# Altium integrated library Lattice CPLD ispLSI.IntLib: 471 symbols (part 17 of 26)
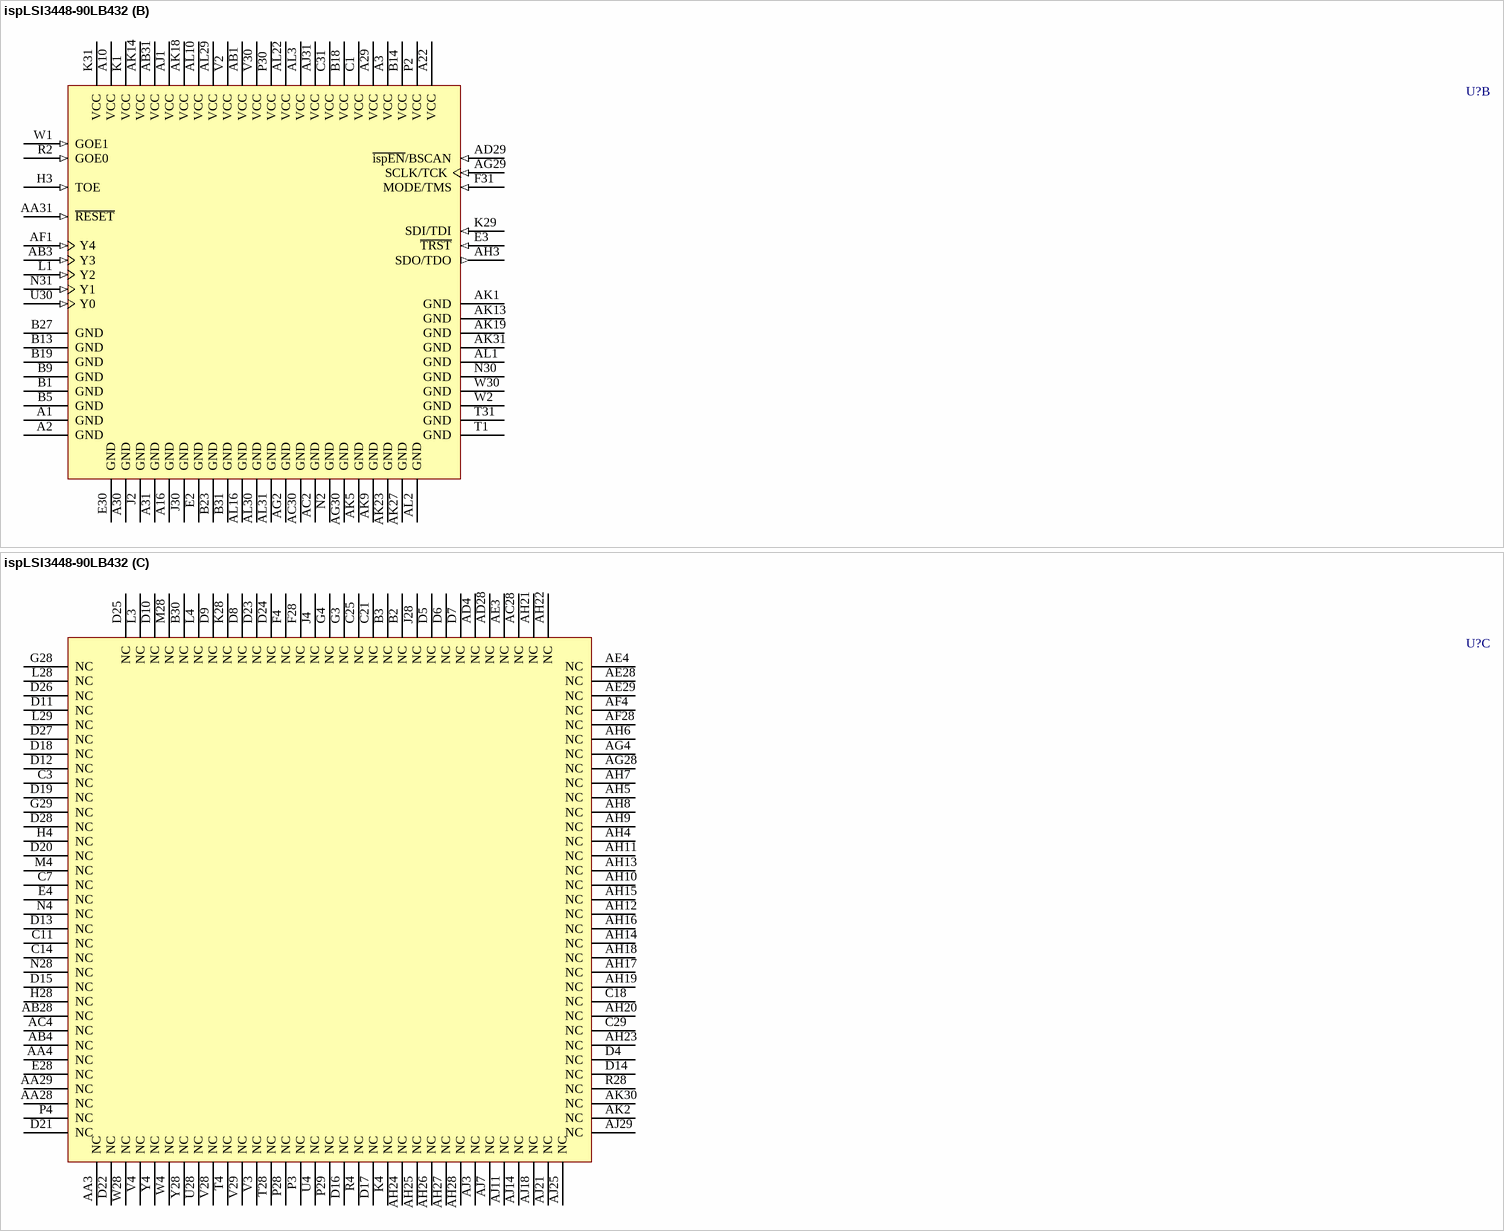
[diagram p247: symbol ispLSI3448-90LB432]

## ispLSI3448-90LB432
designator U?
In-System Programmable High-Density PLD
footprint SBGA432 (BGA, 432-Leads, Body 40x40mm, Pitch 1.27mm)
3D model 3448-SBGA432 (432-Ball Super Ball Grid Array (SBGA432))
part A pins: A4 I/O141 (io), A5 I/O142 (io), A6 I/O145 (io), A7 I/O147 (io), A8 I/O150 (io), A9 I/O152 (io), A11 I/O156 (io), A12 I/O159 (io), A13 I/O161 (io), A14 I/O162 (io), A15 I/O165 (io), A17 I/O170 (io), A18 I/O171 (io), A19 I/O172 (io), A20 I/O174 (io), A21 I/O177 (io), A23 I/O181 (io), A24 I/O183 (io), A25 I/O186 (io), A26 I/O188 (io), A27 I/O191 (io), A28 I/O192 (io), AA1 I/O102 (io), AA2 I/O101 (io), AA30 I/O9 (io), AB2 I/O100 (io), AB29 I/O11 (io), AB30 I/O10 (io), AC1 I/O99 (io), AC3 I/O98 (io), AC29 I/O13 (io), AC31 I/O12 (io), AD1 I/O97 (io), AD2 I/O96 (io), AD3 I/O95 (io), AD30 I/O15 (io), AD31 I/O14 (io), AE1 I/O94 (io), AE2 I/O93 (io), AE30 I/O17 (io), AE31 I/O16 (io), AF2 I/O92 (io), AF3 I/O91 (io), AF29 I/O20 (io), AF30 I/O19 (io), AF31 I/O18 (io), AG1 I/O90 (io), AG3 I/O88 (io), AG31 I/O21 (io), AH1 I/O89 (io), AH2 I/O87 (io), AH29 I/O25 (io), AH30 I/O23 (io), AH31 I/O22 (io), AJ2 I/O86 (io), AJ4 I/O85 (io), AJ5 I/O82 (io), AJ6 I/O79 (io), AJ8 I/O74 (io), AJ9 I/O71 (io), AJ10 I/O69 (io), AJ12 I/O65 (io), AJ13 I/O62 (io), AJ15 I/O57 (io), AJ16 I/O55 (io), AJ17 I/O52 (io), AJ19 I/O49 (io), AJ20 I/O46 (io), AJ22 I/O42 (io), AJ23 I/O40 (io), AJ24 I/O37 (io), AJ26 I/O32 (io), AJ27 I/O29 (io), AJ28 I/O26 (io), AJ30 I/O24 (io), AK3 I/O84 (io), AK4 I/O83 (io), AK6 I/O78 (io), AK7 I/O76 (io), AK8 I/O73 (io), AK10 I/O68 (io), AK11 I/O67 (io), AK12 I/O64 (io), AK15 I/O58 (io), AK16 I/O56 (io), AK17 I/O53 (io), AK20 I/O47 (io), AK21 I/O44 (io), AK22 I/O43 (io), AK24 I/O38 (io), AK25 I/O35 (io), AK26 I/O33 (io), AK28 I/O28 (io), AK29 I/O27 (io), AL4 I/O81 (io), AL5 I/O80 (io), AL6 I/O77 (io), AL7 I/O75 (io), AL8 I/O72 (io), AL9 I/O70 (io), AL11 I/O66 (io), AL12 I/O63 (io), AL13 I/O61 (io), AL14 I/O60 (io), AL15 I/O59 (io), AL17 I/O54 (io), AL18 I/O51 (io), AL19 I/O50 (io), AL20 I/O48 (io), AL21 I/O45 (io), AL23 I/O41 (io), AL24 I/O39 (io), AL25 I/O36 (io), AL26 I/O34 (io), AL27 I/O31 (io), AL28 I/O30 (io), B4 I/O139 (io), B6 I/O144 (io), B7 I/O146 (io), B8 I/O149 (io), B10 I/O154 (io), B11 I/O155 (io), B12 I/O158 (io), B15 I/O164 (io), B16 I/O167 (io), B17 I/O169 (io), B20 I/O175 (io), B21 I/O178 (io), B22 I/O179 (io), B24 I/O184 (io), B25 I/O187 (io), B26 I/O189 (io), B28 I/O194 (io), B29 I/O195 (io), C2 I/O136 (io), C4 I/O138 (io), C5 I/O140 (io), C6 I/O143 (io), C8 I/O148 (io), C9 I/O151 (io), C10 I/O153 (io), C12 I/O157 (io), C13 I/O160 (io), C15 I/O163 (io), C16 I/O166 (io), C17 I/O168 (io), C19 I/O173 (io), C20 I/O176 (io), C22 I/O180 (io), C23 I/O182 (io), C24 I/O185 (io), C26 I/O190 (io), C27 I/O193 (io), C28 I/O196 (io), C30 I/O198 (io), D1 I/O134 (io), D2 I/O135 (io), D3 I/O137 (io), D29 I/O197 (io), D30 I/O199 (io), D31 I/O201 (io), E1 I/O133 (io), E29 I/O200 (io), E31 I/O202 (io), F1 I/O130 (io), F2 I/O131 (io), F3 I/O132 (io), F29 I/O203 (io), F30 I/O204 (io), G1 I/O128 (io), G2 I/O129 (io), G30 I/O205 (io), G31 I/O206 (io), H1 I/O126 (io), H2 I/O127 (io), H29 I/O207 (io), H30 I/O208 (io), H31 I/O209 (io), J1 I/O124 (io), J3 I/O125 (io), J29 I/O210 (io), J31 I/O211 (io), K2 I/O122 (io), K3 I/O123 (io), K30 I/O212 (io), L2 I/O121 (io), L30 I/O213 (io), L31 I/O214 (io), M1 I/O118 (io), M2 I/O119 (io), M3 I/O120 (io), M29 I/O215 (io), M30 I/O216 (io), M31 I/O217 (io), N1 I/O116 (io), N3 I/O117 (io), N29 I/O218 (io), P1 I/O115 (io), P31 I/O219 (io), R1 I/O114 (io), R3 I/O113 (io), R29 I/O220 (io), R30 I/O221 (io), R31 I/O222 (io), T2 I/O112 (io), T3 I/O111 (io), T29 I/O223 (io), T30 I/O0 (io), U1 I/O110 (io), U2 I/O109 (io), U3 I/O108 (io), U29 I/O1 (io), U31 I/O2 (io), V1 I/O107 (io), V31 I/O3 (io), W3 I/O106 (io), W29 I/O5 (io), W31 I/O4 (io), Y1 I/O105 (io), Y2 I/O104 (io), Y3 I/O103 (io), Y29 I/O8 (io), Y30 I/O7 (io), Y31 I/O6 (io)
part B pins: A1 GND (power), A2 GND (power), A3 VCC (power), A10 VCC (power), A16 GND (power), A22 VCC (power), A29 VCC (power), A30 GND (power), A31 GND (power), AA31 ~{RESET} (in), AB1 VCC (power), AB3 Y3 (in), AB31 VCC (power), AC2 GND (power), AC30 GND (power), AD29 ~{ispEN}/BSCAN (in), AF1 Y4 (in), AG2 GND (power), AG29 SCLK/TCK (in), AG30 GND (power), AH3 SDO/TDO (out), AJ1 VCC (power), AJ31 VCC (power), AK1 GND (power), AK5 GND (power), AK9 GND (power), AK13 GND (power), AK14 VCC (power), AK18 VCC (power), AK19 GND (power), AK23 GND (power), AK27 GND (power), AK31 GND (power), AL1 GND (power), AL2 GND (power), AL3 VCC (power), AL10 VCC (power), AL16 GND (power), AL22 VCC (power), AL29 VCC (power), AL30 GND (power), AL31 GND (power), B1 GND (power), B5 GND (power), B9 GND (power), B13 GND (power), B14 VCC (power), B18 VCC (power), B19 GND (power), B23 GND (power), B27 GND (power), B31 GND (power), C1 VCC (power), C31 VCC (power), E2 GND (power), E3 ~{TRST} (in), E30 GND (power), F31 MODE/TMS (in), H3 TOE (in), J2 GND (power), J30 GND (power), K1 VCC (power), K29 SDI/TDI (in), K31 VCC (power), L1 Y2 (in), N2 GND (power), N30 GND (power), N31 Y1 (in), P2 VCC (power), P30 VCC (power), R2 GOE0 (in), T1 GND (power), T31 GND (power), U30 Y0 (in), V2 VCC (power), V30 VCC (power), W1 GOE1 (in), W2 GND (power), W30 GND (power)
part C pins: AA3 NC, AA4 NC, AA28 NC, AA29 NC, AB4 NC, AB28 NC, AC4 NC, AC28 NC, AD4 NC, AD28 NC, AE3 NC, AE4 NC, AE28 NC, AE29 NC, AF4 NC, AF28 NC, AG4 NC, AG28 NC, AH4 NC, AH5 NC, AH6 NC, AH7 NC, AH8 NC, AH9 NC, AH10 NC, AH11 NC, AH12 NC, AH13 NC, AH14 NC, AH15 NC, AH16 NC, AH17 NC, AH18 NC, AH19 NC, AH20 NC, AH21 NC, AH22 NC, AH23 NC, AH24 NC, AH25 NC, AH26 NC, AH27 NC, AH28 NC, AJ3 NC, AJ7 NC, AJ11 NC, AJ14 NC, AJ18 NC, AJ21 NC, AJ25 NC, AJ29 NC, AK2 NC, AK30 NC, B2 NC, B3 NC, B30 NC, C3 NC, C7 NC, C11 NC, C14 NC, C18 NC, C21 NC, C25 NC, C29 NC, D4 NC, D5 NC, D6 NC, D7 NC, D8 NC, D9 NC, D10 NC, D11 NC, D12 NC, D13 NC, D14 NC, D15 NC, D16 NC, D17 NC, D18 NC, D19 NC, D20 NC, D21 NC, D22 NC, D23 NC, D24 NC, D25 NC, D26 NC, D27 NC, D28 NC, E4 NC, E28 NC, F4 NC, F28 NC, G3 NC, G4 NC, G28 NC, G29 NC, H4 NC, H28 NC, J4 NC, J28 NC, K4 NC, K28 NC, L3 NC, L4 NC, L28 NC, L29 NC, M4 NC, M28 NC, N4 NC, N28 NC, P3 NC, P4 NC, P28 NC, P29 NC, R4 NC, R28 NC, T4 NC, T28 NC, U4 NC, U28 NC, V3 NC, V4 NC, V28 NC, V29 NC, W4 NC, W28 NC, Y4 NC, Y28 NC

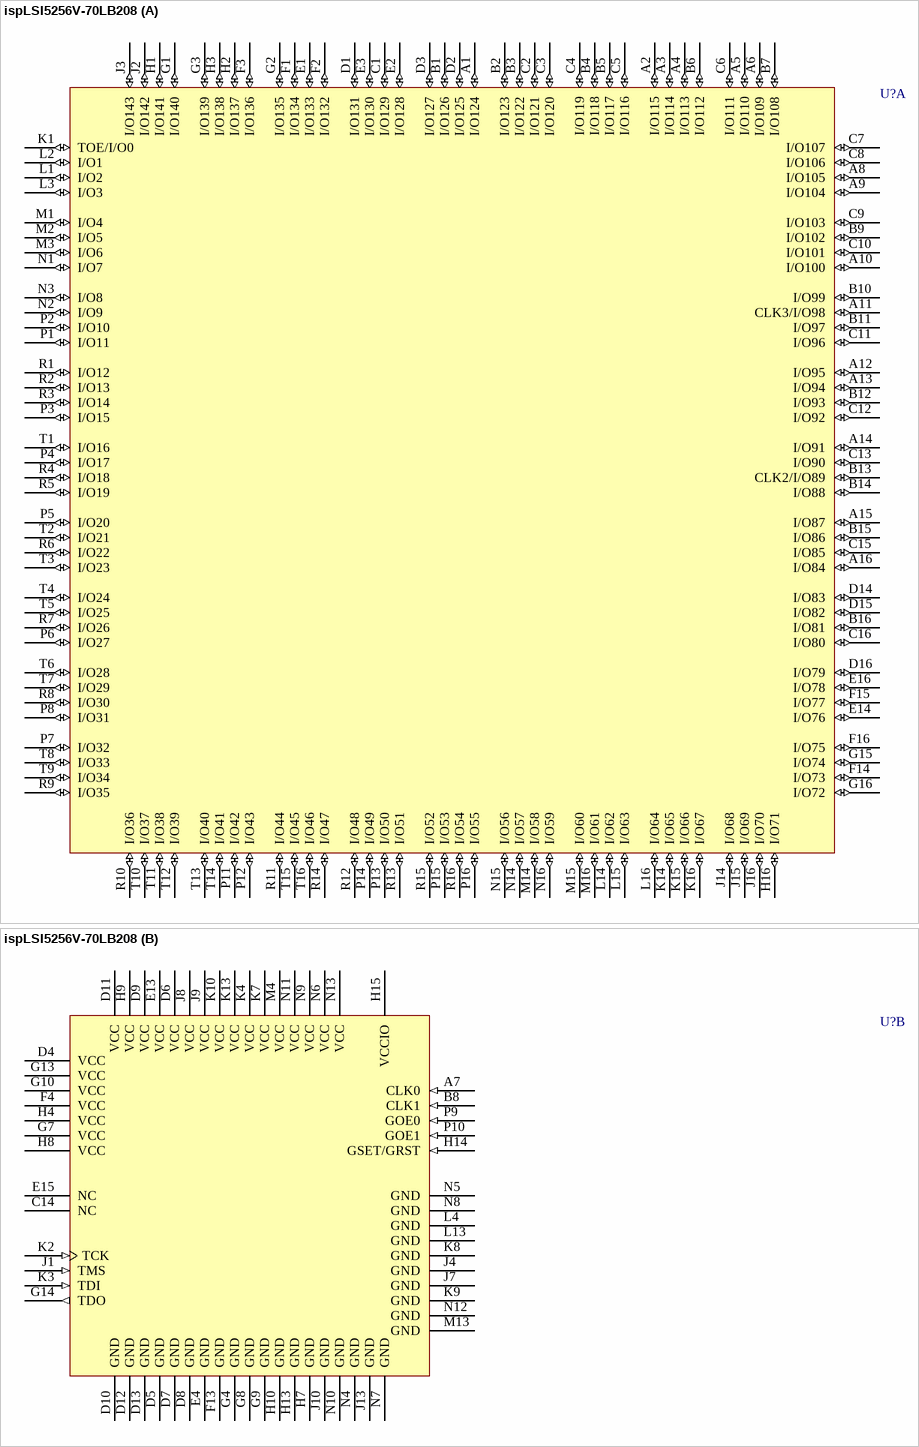
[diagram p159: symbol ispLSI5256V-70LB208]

## ispLSI5256V-70LB208
designator U?
In-System Programmable 3.3V SuperWIDE High-Density PLD; Note: I/O89 is multiplexed with CLK2; I/O98 is multiplexed with CLK3; I/O0 is multiplexed with TOE.
footprint fpBGA208 (BGA, 208-Leads, Body 17x17mm, Pitch 1mm)
3D model 5256V-fpBGA208 (208-Ball Fine Pitch Ball Grid Array (fpBGA208))
part A pins: A1 I/O124 (io), A2 I/O115 (io), A3 I/O114 (io), A4 I/O113 (io), A5 I/O110 (io), A6 I/O109 (io), A8 I/O105 (io), A9 I/O104 (io), A10 I/O100 (io), A11 CLK3/I/O98 (io), A12 I/O95 (io), A13 I/O94 (io), A14 I/O91 (io), A15 I/O87 (io), A16 I/O84 (io), B1 I/O126 (io), B2 I/O123 (io), B3 I/O122 (io), B4 I/O118 (io), B5 I/O117 (io), B6 I/O112 (io), B7 I/O108 (io), B9 I/O102 (io), B10 I/O99 (io), B11 I/O97 (io), B12 I/O93 (io), B13 CLK2/I/O89 (io), B14 I/O88 (io), B15 I/O86 (io), B16 I/O81 (io), C1 I/O129 (io), C2 I/O121 (io), C3 I/O120 (io), C4 I/O119 (io), C5 I/O116 (io), C6 I/O111 (io), C7 I/O107 (io), C8 I/O106 (io), C9 I/O103 (io), C10 I/O101 (io), C11 I/O96 (io), C12 I/O92 (io), C13 I/O90 (io), C15 I/O85 (io), C16 I/O80 (io), D1 I/O131 (io), D2 I/O125 (io), D3 I/O127 (io), D14 I/O83 (io), D15 I/O82 (io), D16 I/O79 (io), E1 I/O133 (io), E2 I/O128 (io), E3 I/O130 (io), E14 I/O76 (io), E16 I/O78 (io), F1 I/O134 (io), F2 I/O132 (io), F3 I/O136 (io), F14 I/O73 (io), F15 I/O77 (io), F16 I/O75 (io), G1 I/O140 (io), G2 I/O135 (io), G3 I/O139 (io), G15 I/O74 (io), G16 I/O72 (io), H1 I/O141 (io), H2 I/O137 (io), H3 I/O138 (io), H16 I/O71 (io), J2 I/O142 (io), J3 I/O143 (io), J14 I/O68 (io), J15 I/O69 (io), J16 I/O70 (io), K1 TOE/I/O0 (io), K14 I/O65 (io), K15 I/O66 (io), K16 I/O67 (io), L1 I/O2 (io), L2 I/O1 (io), L3 I/O3 (io), L14 I/O62 (io), L15 I/O63 (io), L16 I/O64 (io), M1 I/O4 (io), M2 I/O5 (io), M3 I/O6 (io), M14 I/O58 (io), M15 I/O60 (io), M16 I/O61 (io), N1 I/O7 (io), N2 I/O9 (io), N3 I/O8 (io), N14 I/O57 (io), N15 I/O56 (io), N16 I/O59 (io), P1 I/O11 (io), P2 I/O10 (io), P3 I/O15 (io), P4 I/O17 (io), P5 I/O20 (io), P6 I/O27 (io), P7 I/O32 (io), P8 I/O31 (io), P11 I/O42 (io), P12 I/O43 (io), P13 I/O50 (io), P14 I/O49 (io), P15 I/O53 (io), P16 I/O55 (io), R1 I/O12 (io), R2 I/O13 (io), R3 I/O14 (io), R4 I/O18 (io), R5 I/O19 (io), R6 I/O22 (io), R7 I/O26 (io), R8 I/O30 (io), R9 I/O35 (io), R10 I/O36 (io), R11 I/O44 (io), R12 I/O48 (io), R13 I/O51 (io), R14 I/O47 (io), R15 I/O52 (io), R16 I/O54 (io), T1 I/O16 (io), T2 I/O21 (io), T3 I/O23 (io), T4 I/O24 (io), T5 I/O25 (io), T6 I/O28 (io), T7 I/O29 (io), T8 I/O33 (io), T9 I/O34 (io), T10 I/O37 (io), T11 I/O38 (io), T12 I/O39 (io), T13 I/O40 (io), T14 I/O41 (io), T15 I/O45 (io), T16 I/O46 (io)
part B pins: A7 CLK0 (in), B8 CLK1 (in), C14 NC, D4 VCC (power), D5 GND (power), D6 VCC (power), D7 GND (power), D8 GND (power), D9 VCC (power), D10 GND (power), D11 VCC (power), D12 GND (power), D13 GND (power), E4 GND (power), E13 VCC (power), E15 NC, F4 VCC (power), F13 GND (power), G4 GND (power), G7 VCC (power), G8 GND (power), G9 GND (power), G10 VCC (power), G13 VCC (power), G14 TDO (out), H4 VCC (power), H7 GND (power), H8 VCC (power), H9 VCC (power), H10 GND (power), H13 GND (power), H14 GSET/GRST (in), H15 VCCIO (power), J1 TMS (in), J4 GND (power), J7 GND (power), J8 VCC (power), J9 VCC (power), J10 GND (power), J13 GND (power), K2 TCK (in), K3 TDI (in), K4 VCC (power), K7 VCC (power), K8 GND (power), K9 GND (power), K10 VCC (power), K13 VCC (power), L4 GND (power), L13 GND (power), M4 VCC (power), M13 GND (power), N4 GND (power), N5 GND (power), N6 VCC (power), N7 GND (power), N8 GND (power), N9 VCC (power), N10 GND (power), N11 VCC (power), N12 GND (power), N13 VCC (power), P9 GOE0 (in), P10 GOE1 (in)

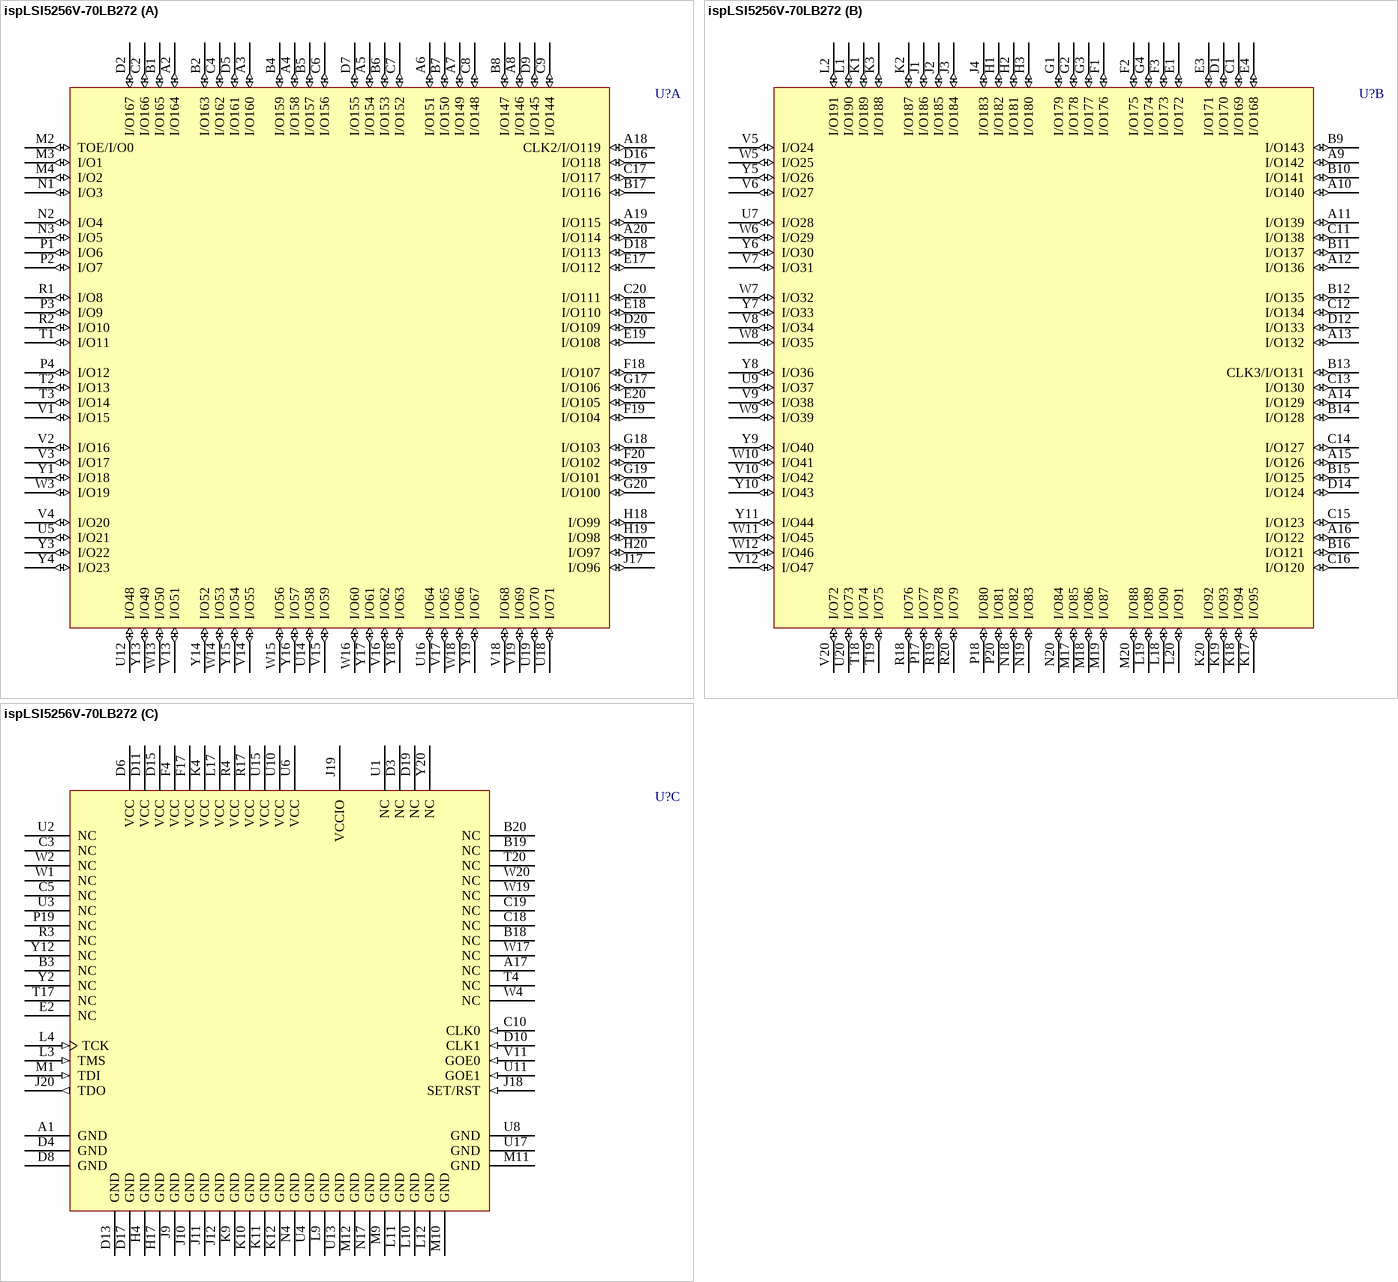
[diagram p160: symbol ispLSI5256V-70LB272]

## ispLSI5256V-70LB272
designator U?
In-System Programmable 3.3V SuperWIDE High-Density PLD; Note: I/O119 is multiplexed with CLK2; I/O131 is multiplexed with CLK3; I/O0 is multiplexed with TOE.
footprint BGA272 (BGA, 272-Leads, Body 27x27mm, Pitch 1.27mm)
3D model 5256V-BGA272 (272-Ball Ball Grid Array (BGA272))
part A pins: A2 I/O164 (io), A3 I/O160 (io), A4 I/O158 (io), A5 I/O154 (io), A6 I/O151 (io), A7 I/O149 (io), A8 I/O146 (io), A18 CLK2/I/O119 (io), A19 I/O115 (io), A20 I/O114 (io), B1 I/O165 (io), B2 I/O163 (io), B4 I/O159 (io), B5 I/O157 (io), B6 I/O153 (io), B7 I/O150 (io), B8 I/O147 (io), B17 I/O116 (io), C2 I/O166 (io), C4 I/O162 (io), C6 I/O156 (io), C7 I/O152 (io), C8 I/O148 (io), C9 I/O144 (io), C17 I/O117 (io), C20 I/O111 (io), D2 I/O167 (io), D5 I/O161 (io), D7 I/O155 (io), D9 I/O145 (io), D16 I/O118 (io), D18 I/O113 (io), D20 I/O109 (io), E17 I/O112 (io), E18 I/O110 (io), E19 I/O108 (io), E20 I/O105 (io), F18 I/O107 (io), F19 I/O104 (io), F20 I/O102 (io), G17 I/O106 (io), G18 I/O103 (io), G19 I/O101 (io), G20 I/O100 (io), H18 I/O99 (io), H19 I/O98 (io), H20 I/O97 (io), J17 I/O96 (io), M2 TOE/I/O0 (io), M3 I/O1 (io), M4 I/O2 (io), N1 I/O3 (io), N2 I/O4 (io), N3 I/O5 (io), P1 I/O6 (io), P2 I/O7 (io), P3 I/O9 (io), P4 I/O12 (io), R1 I/O8 (io), R2 I/O10 (io), T1 I/O11 (io), T2 I/O13 (io), T3 I/O14 (io), U5 I/O21 (io), U12 I/O48 (io), U14 I/O58 (io), U16 I/O64 (io), U18 I/O71 (io), U19 I/O70 (io), V1 I/O15 (io), V2 I/O16 (io), V3 I/O17 (io), V4 I/O20 (io), V13 I/O51 (io), V14 I/O55 (io), V15 I/O59 (io), V16 I/O62 (io), V17 I/O65 (io), V18 I/O68 (io), V19 I/O69 (io), W3 I/O19 (io), W13 I/O50 (io), W14 I/O53 (io), W15 I/O56 (io), W16 I/O60 (io), W18 I/O66 (io), Y1 I/O18 (io), Y3 I/O22 (io), Y4 I/O23 (io), Y13 I/O49 (io), Y14 I/O52 (io), Y15 I/O54 (io), Y16 I/O57 (io), Y17 I/O61 (io), Y18 I/O63 (io), Y19 I/O67 (io)
part B pins: A9 I/O142 (io), A10 I/O140 (io), A11 I/O139 (io), A12 I/O136 (io), A13 I/O132 (io), A14 I/O129 (io), A15 I/O126 (io), A16 I/O122 (io), B9 I/O143 (io), B10 I/O141 (io), B11 I/O137 (io), B12 I/O135 (io), B13 CLK3/I/O131 (io), B14 I/O128 (io), B15 I/O125 (io), B16 I/O121 (io), C1 I/O169 (io), C11 I/O138 (io), C12 I/O134 (io), C13 I/O130 (io), C14 I/O127 (io), C15 I/O123 (io), C16 I/O120 (io), D1 I/O170 (io), D12 I/O133 (io), D14 I/O124 (io), E1 I/O172 (io), E3 I/O171 (io), E4 I/O168 (io), F1 I/O176 (io), F2 I/O175 (io), F3 I/O173 (io), G1 I/O179 (io), G2 I/O178 (io), G3 I/O177 (io), G4 I/O174 (io), H1 I/O182 (io), H2 I/O181 (io), H3 I/O180 (io), J1 I/O186 (io), J2 I/O185 (io), J3 I/O184 (io), J4 I/O183 (io), K1 I/O189 (io), K2 I/O187 (io), K3 I/O188 (io), K17 I/O95 (io), K18 I/O94 (io), K19 I/O93 (io), K20 I/O92 (io), L1 I/O190 (io), L2 I/O191 (io), L18 I/O90 (io), L19 I/O89 (io), L20 I/O91 (io), M17 I/O85 (io), M18 I/O86 (io), M19 I/O87 (io), M20 I/O88 (io), N18 I/O82 (io), N19 I/O83 (io), N20 I/O84 (io), P17 I/O77 (io), P18 I/O80 (io), P20 I/O81 (io), R18 I/O76 (io), R19 I/O78 (io), R20 I/O79 (io), T18 I/O74 (io), T19 I/O75 (io), U7 I/O28 (io), U9 I/O37 (io), U20 I/O73 (io), V5 I/O24 (io), V6 I/O27 (io), V7 I/O31 (io), V8 I/O34 (io), V9 I/O38 (io), V10 I/O42 (io), V12 I/O47 (io), V20 I/O72 (io), W5 I/O25 (io), W6 I/O29 (io), W7 I/O32 (io), W8 I/O35 (io), W9 I/O39 (io), W10 I/O41 (io), W11 I/O45 (io), W12 I/O46 (io), Y5 I/O26 (io), Y6 I/O30 (io), Y7 I/O33 (io), Y8 I/O36 (io), Y9 I/O40 (io), Y10 I/O43 (io), Y11 I/O44 (io)
part C pins: A1 GND (power), A17 NC, B3 NC, B18 NC, B19 NC, B20 NC, C3 NC, C5 NC, C10 CLK0 (in), C18 NC, C19 NC, D3 NC, D4 GND (power), D6 VCC (power), D8 GND (power), D10 CLK1 (in), D11 VCC (power), D13 GND (power), D15 VCC (power), D17 GND (power), D19 NC, E2 NC, F4 VCC (power), F17 VCC (power), H4 GND (power), H17 GND (power), J9 GND (power), J10 GND (power), J11 GND (power), J12 GND (power), J18 SET/RST (in), J19 VCCIO (power), J20 TDO (out), K4 VCC (power), K9 GND (power), K10 GND (power), K11 GND (power), K12 GND (power), L3 TMS (in), L4 TCK (in), L9 GND (power), L10 GND (power), L11 GND (power), L12 GND (power), L17 VCC (power), M1 TDI (in), M9 GND (power), M10 GND (power), M11 GND (power), M12 GND (power), N4 GND (power), N17 GND (power), P19 NC, R3 NC, R4 VCC (power), R17 VCC (power), T4 NC, T17 NC, T20 NC, U1 NC, U2 NC, U3 NC, U4 GND (power), U6 VCC (power), U8 GND (power), U10 VCC (power), U11 GOE1 (in), U13 GND (power), U15 VCC (power), U17 GND (power), V11 GOE0 (in), W1 NC, W2 NC, W4 NC, W17 NC, W19 NC, W20 NC, Y2 NC, Y12 NC, Y20 NC

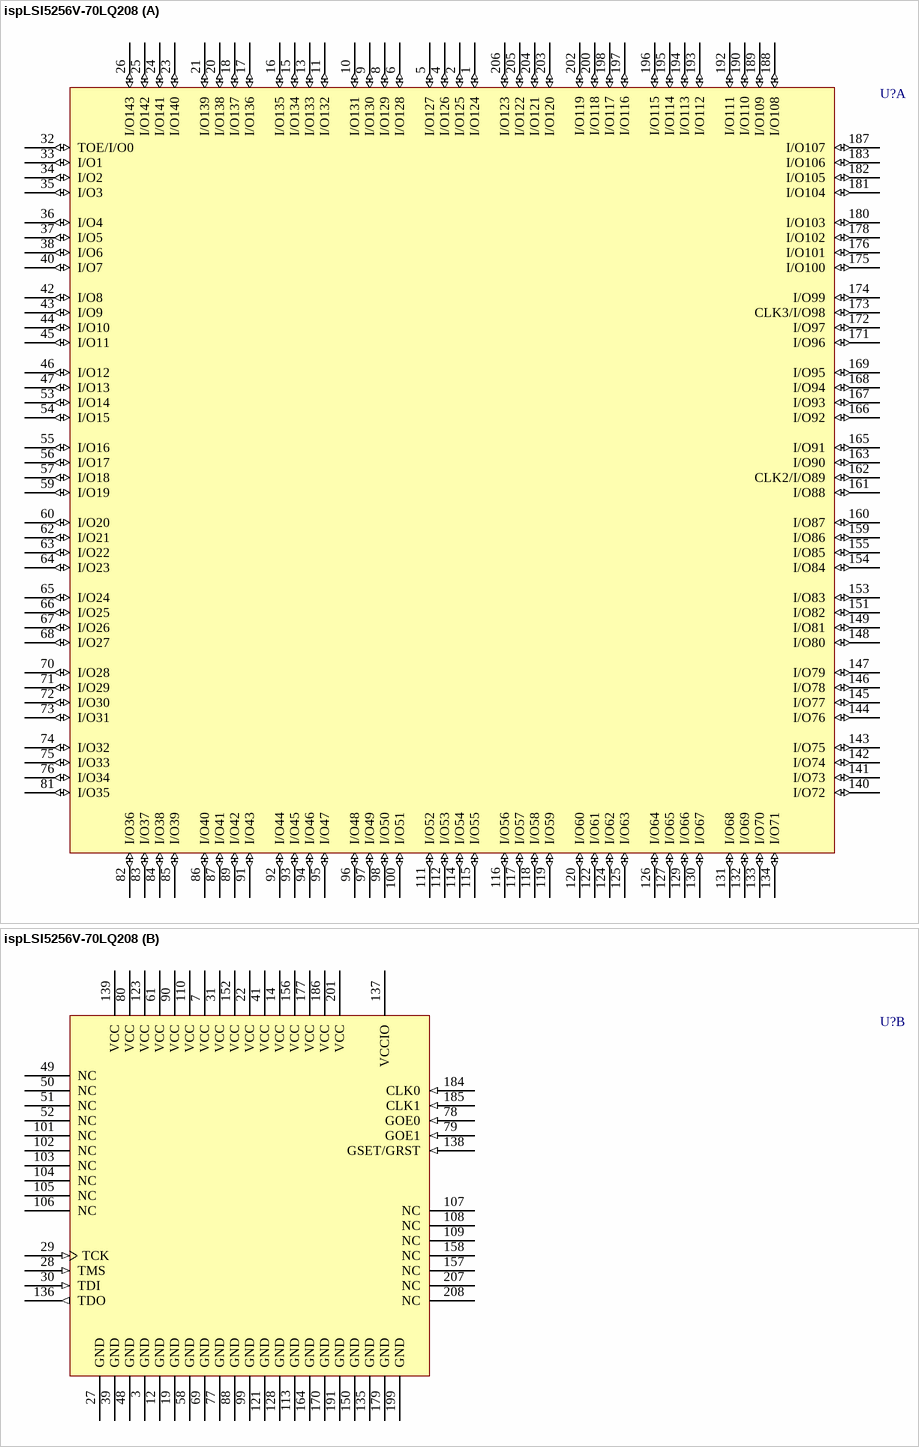
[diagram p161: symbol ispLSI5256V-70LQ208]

## ispLSI5256V-70LQ208
designator U?
In-System Programmable 3.3V SuperWIDE High-Density PLD; Note: I/O89 is multiplexed with CLK2; I/O98 is multiplexed with CLK3; I/O0 is multiplexed with TOE.
footprint PQFP208_N (Shrink QFP, 208-Leads, Body 28x28mm, Pitch 0.5mm, IPC Medium Density)
footprint PQFP208_L (Shrink QFP, 208-Leads, Body 28x28mm, Pitch 0.5mm, IPC High Density)
footprint PQFP208_M (Shrink QFP, 208-Leads, Body 28x28mm, Pitch 0.5mm, IPC Low Density)
3D model 5256V-PQFP208 (208-Pin Plastic Quad Flat Pack (PQFP208))
part A pins: 1 I/O124 (io), 2 I/O125 (io), 4 I/O126 (io), 5 I/O127 (io), 6 I/O128 (io), 8 I/O129 (io), 9 I/O130 (io), 10 I/O131 (io), 11 I/O132 (io), 13 I/O133 (io), 15 I/O134 (io), 16 I/O135 (io), 17 I/O136 (io), 18 I/O137 (io), 20 I/O138 (io), 21 I/O139 (io), 23 I/O140 (io), 24 I/O141 (io), 25 I/O142 (io), 26 I/O143 (io), 32 TOE/I/O0 (io), 33 I/O1 (io), 34 I/O2 (io), 35 I/O3 (io), 36 I/O4 (io), 37 I/O5 (io), 38 I/O6 (io), 40 I/O7 (io), 42 I/O8 (io), 43 I/O9 (io), 44 I/O10 (io), 45 I/O11 (io), 46 I/O12 (io), 47 I/O13 (io), 53 I/O14 (io), 54 I/O15 (io), 55 I/O16 (io), 56 I/O17 (io), 57 I/O18 (io), 59 I/O19 (io), 60 I/O20 (io), 62 I/O21 (io), 63 I/O22 (io), 64 I/O23 (io), 65 I/O24 (io), 66 I/O25 (io), 67 I/O26 (io), 68 I/O27 (io), 70 I/O28 (io), 71 I/O29 (io), 72 I/O30 (io), 73 I/O31 (io), 74 I/O32 (io), 75 I/O33 (io), 76 I/O34 (io), 81 I/O35 (io), 82 I/O36 (io), 83 I/O37 (io), 84 I/O38 (io), 85 I/O39 (io), 86 I/O40 (io), 87 I/O41 (io), 89 I/O42 (io), 91 I/O43 (io), 92 I/O44 (io), 93 I/O45 (io), 94 I/O46 (io), 95 I/O47 (io), 96 I/O48 (io), 97 I/O49 (io), 98 I/O50 (io), 100 I/O51 (io), 111 I/O52 (io), 112 I/O53 (io), 114 I/O54 (io), 115 I/O55 (io), 116 I/O56 (io), 117 I/O57 (io), 118 I/O58 (io), 119 I/O59 (io), 120 I/O60 (io), 122 I/O61 (io), 124 I/O62 (io), 125 I/O63 (io), 126 I/O64 (io), 127 I/O65 (io), 129 I/O66 (io), 130 I/O67 (io), 131 I/O68 (io), 132 I/O69 (io), 133 I/O70 (io), 134 I/O71 (io), 140 I/O72 (io), 141 I/O73 (io), 142 I/O74 (io), 143 I/O75 (io), 144 I/O76 (io), 145 I/O77 (io), 146 I/O78 (io), 147 I/O79 (io), 148 I/O80 (io), 149 I/O81 (io), 151 I/O82 (io), 153 I/O83 (io), 154 I/O84 (io), 155 I/O85 (io), 159 I/O86 (io), 160 I/O87 (io), 161 I/O88 (io), 162 CLK2/I/O89 (io), 163 I/O90 (io), 165 I/O91 (io), 166 I/O92 (io), 167 I/O93 (io), 168 I/O94 (io), 169 I/O95 (io), 171 I/O96 (io), 172 I/O97 (io), 173 CLK3/I/O98 (io), 174 I/O99 (io), 175 I/O100 (io), 176 I/O101 (io), 178 I/O102 (io), 180 I/O103 (io), 181 I/O104 (io), 182 I/O105 (io), 183 I/O106 (io), 187 I/O107 (io), 188 I/O108 (io), 189 I/O109 (io), 190 I/O110 (io), 192 I/O111 (io), 193 I/O112 (io), 194 I/O113 (io), 195 I/O114 (io), 196 I/O115 (io), 197 I/O116 (io), 198 I/O117 (io), 200 I/O118 (io), 202 I/O119 (io), 203 I/O120 (io), 204 I/O121 (io), 205 I/O122 (io), 206 I/O123 (io)
part B pins: 3 GND (power), 7 VCC (power), 12 GND (power), 14 VCC (power), 19 GND (power), 22 VCC (power), 27 GND (power), 28 TMS (in), 29 TCK (in), 30 TDI (in), 31 VCC (power), 39 GND (power), 41 VCC (power), 48 GND (power), 49 NC, 50 NC, 51 NC, 52 NC, 58 GND (power), 61 VCC (power), 69 GND (power), 77 GND (power), 78 GOE0 (in), 79 GOE1 (in), 80 VCC (power), 88 GND (power), 90 VCC (power), 99 GND (power), 101 NC, 102 NC, 103 NC, 104 NC, 105 NC, 106 NC, 107 NC, 108 NC, 109 NC, 110 VCC (power), 113 GND (power), 121 GND (power), 123 VCC (power), 128 GND (power), 135 GND (power), 136 TDO (out), 137 VCCIO (power), 138 GSET/GRST (in), 139 VCC (power), 150 GND (power), 152 VCC (power), 156 VCC (power), 157 NC, 158 NC, 164 GND (power), 170 GND (power), 177 VCC (power), 179 GND (power), 184 CLK0 (in), 185 CLK1 (in), 186 VCC (power), 191 GND (power), 199 GND (power), 201 VCC (power), 207 NC, 208 NC

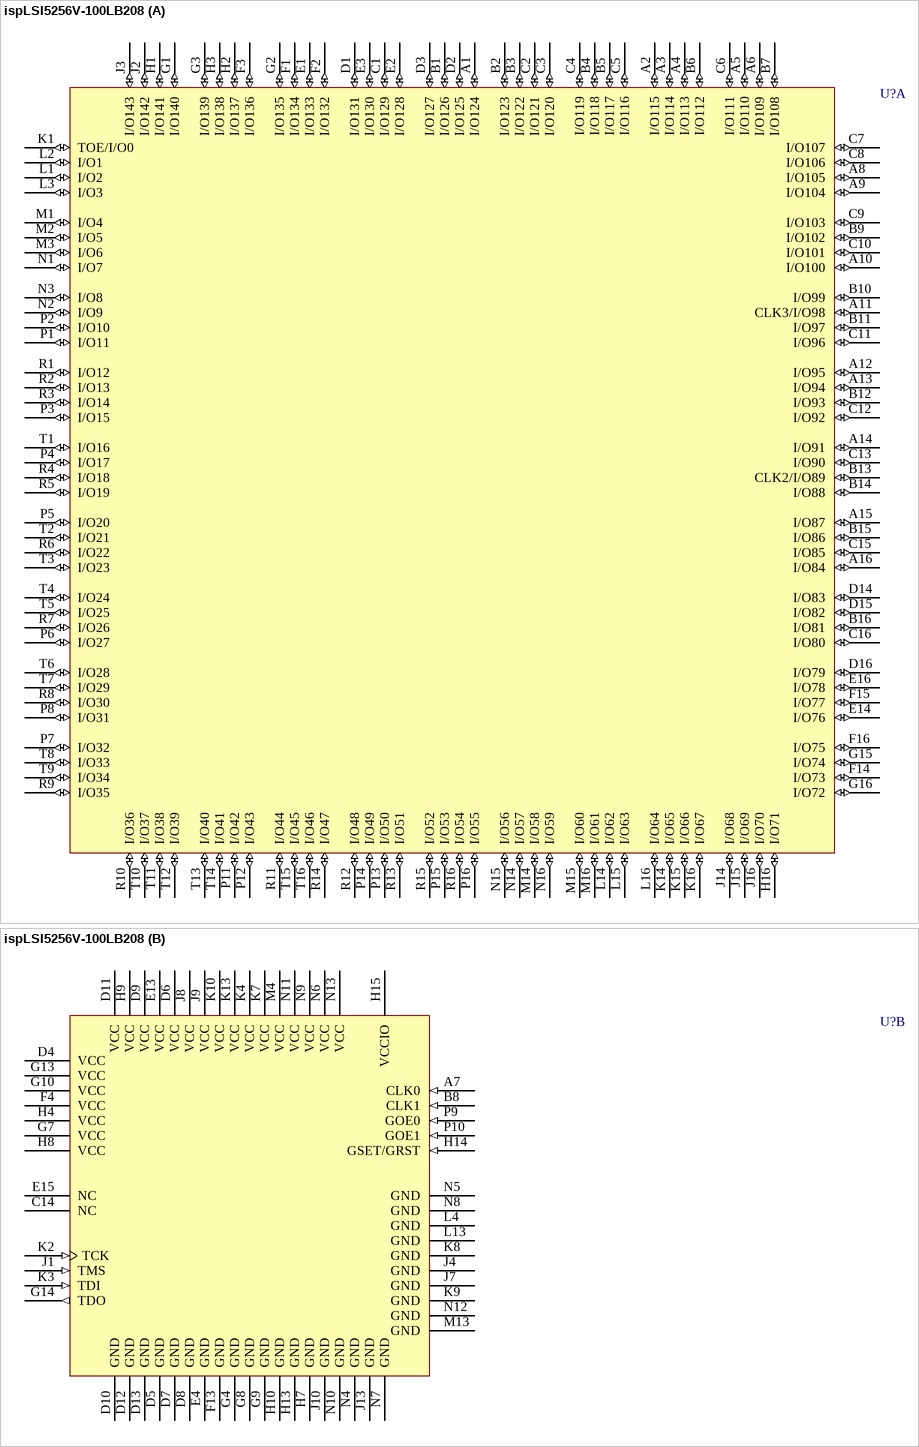
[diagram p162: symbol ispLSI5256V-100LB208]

## ispLSI5256V-100LB208
designator U?
In-System Programmable 3.3V SuperWIDE High-Density PLD; Note: I/O89 is multiplexed with CLK2; I/O98 is multiplexed with CLK3; I/O0 is multiplexed with TOE.
footprint fpBGA208 (BGA, 208-Leads, Body 17x17mm, Pitch 1mm)
3D model 5256V-fpBGA208 (208-Ball Fine Pitch Ball Grid Array (fpBGA208))
part A pins: A1 I/O124 (io), A2 I/O115 (io), A3 I/O114 (io), A4 I/O113 (io), A5 I/O110 (io), A6 I/O109 (io), A8 I/O105 (io), A9 I/O104 (io), A10 I/O100 (io), A11 CLK3/I/O98 (io), A12 I/O95 (io), A13 I/O94 (io), A14 I/O91 (io), A15 I/O87 (io), A16 I/O84 (io), B1 I/O126 (io), B2 I/O123 (io), B3 I/O122 (io), B4 I/O118 (io), B5 I/O117 (io), B6 I/O112 (io), B7 I/O108 (io), B9 I/O102 (io), B10 I/O99 (io), B11 I/O97 (io), B12 I/O93 (io), B13 CLK2/I/O89 (io), B14 I/O88 (io), B15 I/O86 (io), B16 I/O81 (io), C1 I/O129 (io), C2 I/O121 (io), C3 I/O120 (io), C4 I/O119 (io), C5 I/O116 (io), C6 I/O111 (io), C7 I/O107 (io), C8 I/O106 (io), C9 I/O103 (io), C10 I/O101 (io), C11 I/O96 (io), C12 I/O92 (io), C13 I/O90 (io), C15 I/O85 (io), C16 I/O80 (io), D1 I/O131 (io), D2 I/O125 (io), D3 I/O127 (io), D14 I/O83 (io), D15 I/O82 (io), D16 I/O79 (io), E1 I/O133 (io), E2 I/O128 (io), E3 I/O130 (io), E14 I/O76 (io), E16 I/O78 (io), F1 I/O134 (io), F2 I/O132 (io), F3 I/O136 (io), F14 I/O73 (io), F15 I/O77 (io), F16 I/O75 (io), G1 I/O140 (io), G2 I/O135 (io), G3 I/O139 (io), G15 I/O74 (io), G16 I/O72 (io), H1 I/O141 (io), H2 I/O137 (io), H3 I/O138 (io), H16 I/O71 (io), J2 I/O142 (io), J3 I/O143 (io), J14 I/O68 (io), J15 I/O69 (io), J16 I/O70 (io), K1 TOE/I/O0 (io), K14 I/O65 (io), K15 I/O66 (io), K16 I/O67 (io), L1 I/O2 (io), L2 I/O1 (io), L3 I/O3 (io), L14 I/O62 (io), L15 I/O63 (io), L16 I/O64 (io), M1 I/O4 (io), M2 I/O5 (io), M3 I/O6 (io), M14 I/O58 (io), M15 I/O60 (io), M16 I/O61 (io), N1 I/O7 (io), N2 I/O9 (io), N3 I/O8 (io), N14 I/O57 (io), N15 I/O56 (io), N16 I/O59 (io), P1 I/O11 (io), P2 I/O10 (io), P3 I/O15 (io), P4 I/O17 (io), P5 I/O20 (io), P6 I/O27 (io), P7 I/O32 (io), P8 I/O31 (io), P11 I/O42 (io), P12 I/O43 (io), P13 I/O50 (io), P14 I/O49 (io), P15 I/O53 (io), P16 I/O55 (io), R1 I/O12 (io), R2 I/O13 (io), R3 I/O14 (io), R4 I/O18 (io), R5 I/O19 (io), R6 I/O22 (io), R7 I/O26 (io), R8 I/O30 (io), R9 I/O35 (io), R10 I/O36 (io), R11 I/O44 (io), R12 I/O48 (io), R13 I/O51 (io), R14 I/O47 (io), R15 I/O52 (io), R16 I/O54 (io), T1 I/O16 (io), T2 I/O21 (io), T3 I/O23 (io), T4 I/O24 (io), T5 I/O25 (io), T6 I/O28 (io), T7 I/O29 (io), T8 I/O33 (io), T9 I/O34 (io), T10 I/O37 (io), T11 I/O38 (io), T12 I/O39 (io), T13 I/O40 (io), T14 I/O41 (io), T15 I/O45 (io), T16 I/O46 (io)
part B pins: A7 CLK0 (in), B8 CLK1 (in), C14 NC, D4 VCC (power), D5 GND (power), D6 VCC (power), D7 GND (power), D8 GND (power), D9 VCC (power), D10 GND (power), D11 VCC (power), D12 GND (power), D13 GND (power), E4 GND (power), E13 VCC (power), E15 NC, F4 VCC (power), F13 GND (power), G4 GND (power), G7 VCC (power), G8 GND (power), G9 GND (power), G10 VCC (power), G13 VCC (power), G14 TDO (out), H4 VCC (power), H7 GND (power), H8 VCC (power), H9 VCC (power), H10 GND (power), H13 GND (power), H14 GSET/GRST (in), H15 VCCIO (power), J1 TMS (in), J4 GND (power), J7 GND (power), J8 VCC (power), J9 VCC (power), J10 GND (power), J13 GND (power), K2 TCK (in), K3 TDI (in), K4 VCC (power), K7 VCC (power), K8 GND (power), K9 GND (power), K10 VCC (power), K13 VCC (power), L4 GND (power), L13 GND (power), M4 VCC (power), M13 GND (power), N4 GND (power), N5 GND (power), N6 VCC (power), N7 GND (power), N8 GND (power), N9 VCC (power), N10 GND (power), N11 VCC (power), N12 GND (power), N13 VCC (power), P9 GOE0 (in), P10 GOE1 (in)

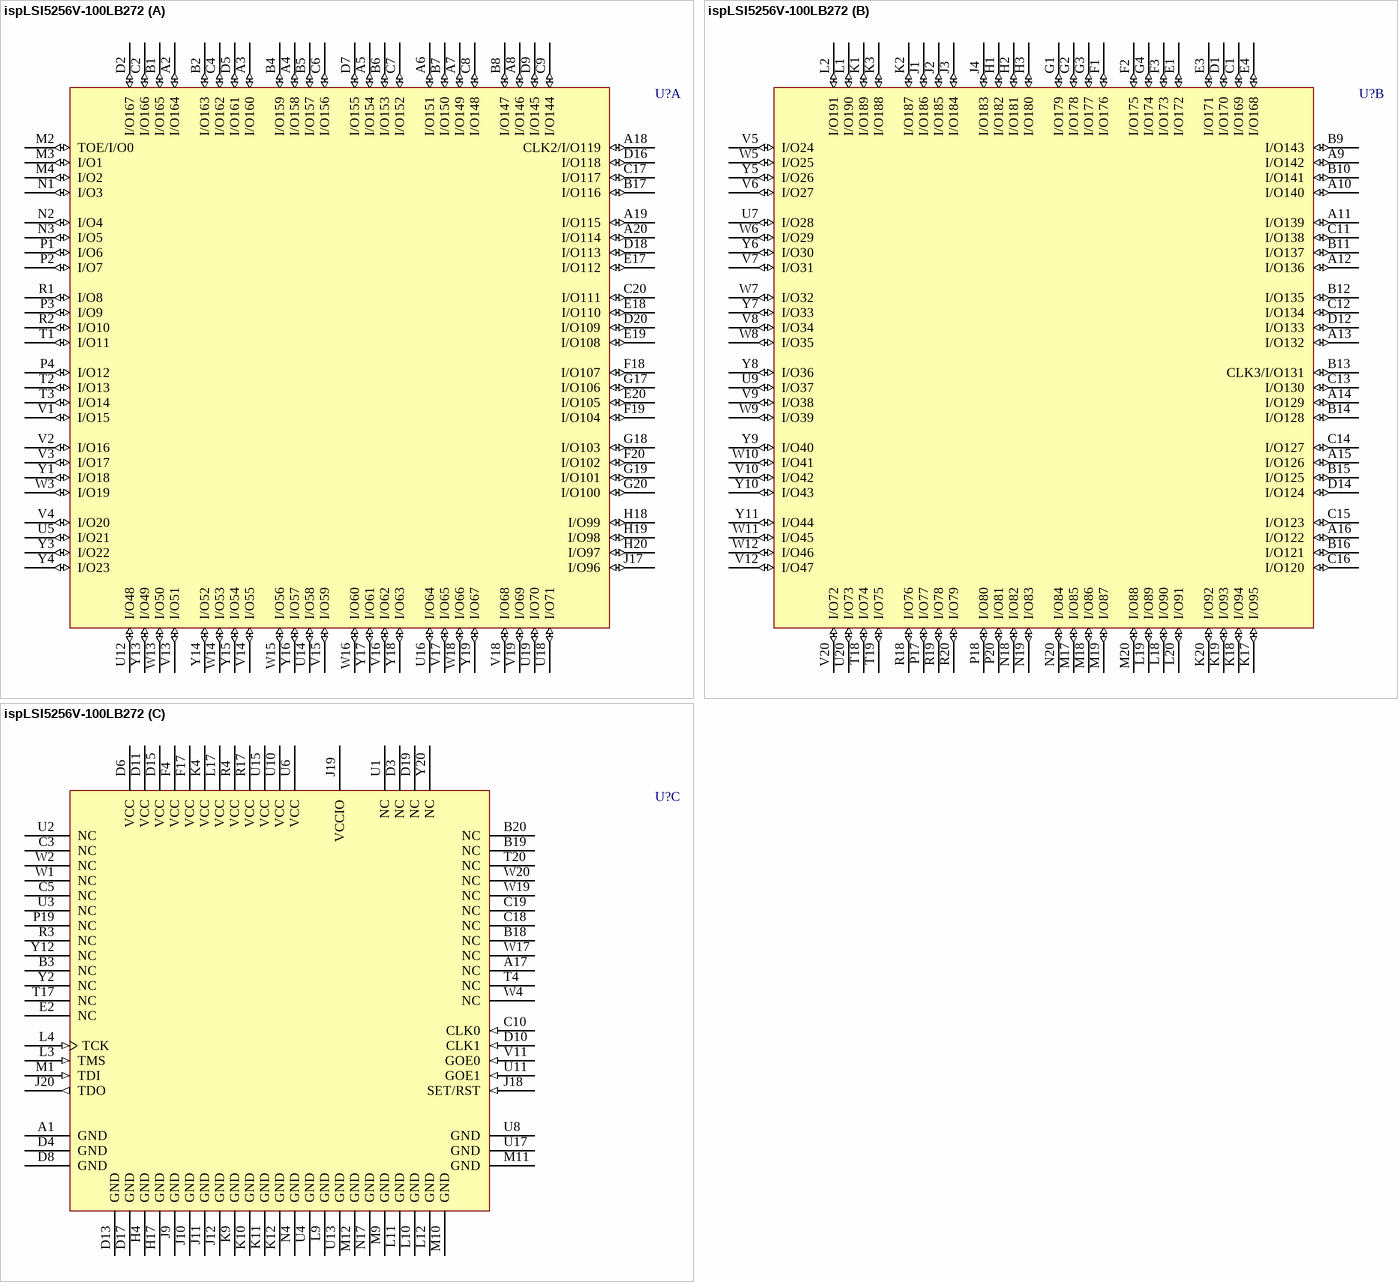
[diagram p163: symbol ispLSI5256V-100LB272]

## ispLSI5256V-100LB272
designator U?
In-System Programmable 3.3V SuperWIDE High-Density PLD; Note: I/O119 is multiplexed with CLK2; I/O131 is multiplexed with CLK3; I/O0 is multiplexed with TOE.
footprint BGA272 (BGA, 272-Leads, Body 27x27mm, Pitch 1.27mm)
3D model 5256V-BGA272 (272-Ball Ball Grid Array (BGA272))
part A pins: A2 I/O164 (io), A3 I/O160 (io), A4 I/O158 (io), A5 I/O154 (io), A6 I/O151 (io), A7 I/O149 (io), A8 I/O146 (io), A18 CLK2/I/O119 (io), A19 I/O115 (io), A20 I/O114 (io), B1 I/O165 (io), B2 I/O163 (io), B4 I/O159 (io), B5 I/O157 (io), B6 I/O153 (io), B7 I/O150 (io), B8 I/O147 (io), B17 I/O116 (io), C2 I/O166 (io), C4 I/O162 (io), C6 I/O156 (io), C7 I/O152 (io), C8 I/O148 (io), C9 I/O144 (io), C17 I/O117 (io), C20 I/O111 (io), D2 I/O167 (io), D5 I/O161 (io), D7 I/O155 (io), D9 I/O145 (io), D16 I/O118 (io), D18 I/O113 (io), D20 I/O109 (io), E17 I/O112 (io), E18 I/O110 (io), E19 I/O108 (io), E20 I/O105 (io), F18 I/O107 (io), F19 I/O104 (io), F20 I/O102 (io), G17 I/O106 (io), G18 I/O103 (io), G19 I/O101 (io), G20 I/O100 (io), H18 I/O99 (io), H19 I/O98 (io), H20 I/O97 (io), J17 I/O96 (io), M2 TOE/I/O0 (io), M3 I/O1 (io), M4 I/O2 (io), N1 I/O3 (io), N2 I/O4 (io), N3 I/O5 (io), P1 I/O6 (io), P2 I/O7 (io), P3 I/O9 (io), P4 I/O12 (io), R1 I/O8 (io), R2 I/O10 (io), T1 I/O11 (io), T2 I/O13 (io), T3 I/O14 (io), U5 I/O21 (io), U12 I/O48 (io), U14 I/O58 (io), U16 I/O64 (io), U18 I/O71 (io), U19 I/O70 (io), V1 I/O15 (io), V2 I/O16 (io), V3 I/O17 (io), V4 I/O20 (io), V13 I/O51 (io), V14 I/O55 (io), V15 I/O59 (io), V16 I/O62 (io), V17 I/O65 (io), V18 I/O68 (io), V19 I/O69 (io), W3 I/O19 (io), W13 I/O50 (io), W14 I/O53 (io), W15 I/O56 (io), W16 I/O60 (io), W18 I/O66 (io), Y1 I/O18 (io), Y3 I/O22 (io), Y4 I/O23 (io), Y13 I/O49 (io), Y14 I/O52 (io), Y15 I/O54 (io), Y16 I/O57 (io), Y17 I/O61 (io), Y18 I/O63 (io), Y19 I/O67 (io)
part B pins: A9 I/O142 (io), A10 I/O140 (io), A11 I/O139 (io), A12 I/O136 (io), A13 I/O132 (io), A14 I/O129 (io), A15 I/O126 (io), A16 I/O122 (io), B9 I/O143 (io), B10 I/O141 (io), B11 I/O137 (io), B12 I/O135 (io), B13 CLK3/I/O131 (io), B14 I/O128 (io), B15 I/O125 (io), B16 I/O121 (io), C1 I/O169 (io), C11 I/O138 (io), C12 I/O134 (io), C13 I/O130 (io), C14 I/O127 (io), C15 I/O123 (io), C16 I/O120 (io), D1 I/O170 (io), D12 I/O133 (io), D14 I/O124 (io), E1 I/O172 (io), E3 I/O171 (io), E4 I/O168 (io), F1 I/O176 (io), F2 I/O175 (io), F3 I/O173 (io), G1 I/O179 (io), G2 I/O178 (io), G3 I/O177 (io), G4 I/O174 (io), H1 I/O182 (io), H2 I/O181 (io), H3 I/O180 (io), J1 I/O186 (io), J2 I/O185 (io), J3 I/O184 (io), J4 I/O183 (io), K1 I/O189 (io), K2 I/O187 (io), K3 I/O188 (io), K17 I/O95 (io), K18 I/O94 (io), K19 I/O93 (io), K20 I/O92 (io), L1 I/O190 (io), L2 I/O191 (io), L18 I/O90 (io), L19 I/O89 (io), L20 I/O91 (io), M17 I/O85 (io), M18 I/O86 (io), M19 I/O87 (io), M20 I/O88 (io), N18 I/O82 (io), N19 I/O83 (io), N20 I/O84 (io), P17 I/O77 (io), P18 I/O80 (io), P20 I/O81 (io), R18 I/O76 (io), R19 I/O78 (io), R20 I/O79 (io), T18 I/O74 (io), T19 I/O75 (io), U7 I/O28 (io), U9 I/O37 (io), U20 I/O73 (io), V5 I/O24 (io), V6 I/O27 (io), V7 I/O31 (io), V8 I/O34 (io), V9 I/O38 (io), V10 I/O42 (io), V12 I/O47 (io), V20 I/O72 (io), W5 I/O25 (io), W6 I/O29 (io), W7 I/O32 (io), W8 I/O35 (io), W9 I/O39 (io), W10 I/O41 (io), W11 I/O45 (io), W12 I/O46 (io), Y5 I/O26 (io), Y6 I/O30 (io), Y7 I/O33 (io), Y8 I/O36 (io), Y9 I/O40 (io), Y10 I/O43 (io), Y11 I/O44 (io)
part C pins: A1 GND (power), A17 NC, B3 NC, B18 NC, B19 NC, B20 NC, C3 NC, C5 NC, C10 CLK0 (in), C18 NC, C19 NC, D3 NC, D4 GND (power), D6 VCC (power), D8 GND (power), D10 CLK1 (in), D11 VCC (power), D13 GND (power), D15 VCC (power), D17 GND (power), D19 NC, E2 NC, F4 VCC (power), F17 VCC (power), H4 GND (power), H17 GND (power), J9 GND (power), J10 GND (power), J11 GND (power), J12 GND (power), J18 SET/RST (in), J19 VCCIO (power), J20 TDO (out), K4 VCC (power), K9 GND (power), K10 GND (power), K11 GND (power), K12 GND (power), L3 TMS (in), L4 TCK (in), L9 GND (power), L10 GND (power), L11 GND (power), L12 GND (power), L17 VCC (power), M1 TDI (in), M9 GND (power), M10 GND (power), M11 GND (power), M12 GND (power), N4 GND (power), N17 GND (power), P19 NC, R3 NC, R4 VCC (power), R17 VCC (power), T4 NC, T17 NC, T20 NC, U1 NC, U2 NC, U3 NC, U4 GND (power), U6 VCC (power), U8 GND (power), U10 VCC (power), U11 GOE1 (in), U13 GND (power), U15 VCC (power), U17 GND (power), V11 GOE0 (in), W1 NC, W2 NC, W4 NC, W17 NC, W19 NC, W20 NC, Y2 NC, Y12 NC, Y20 NC

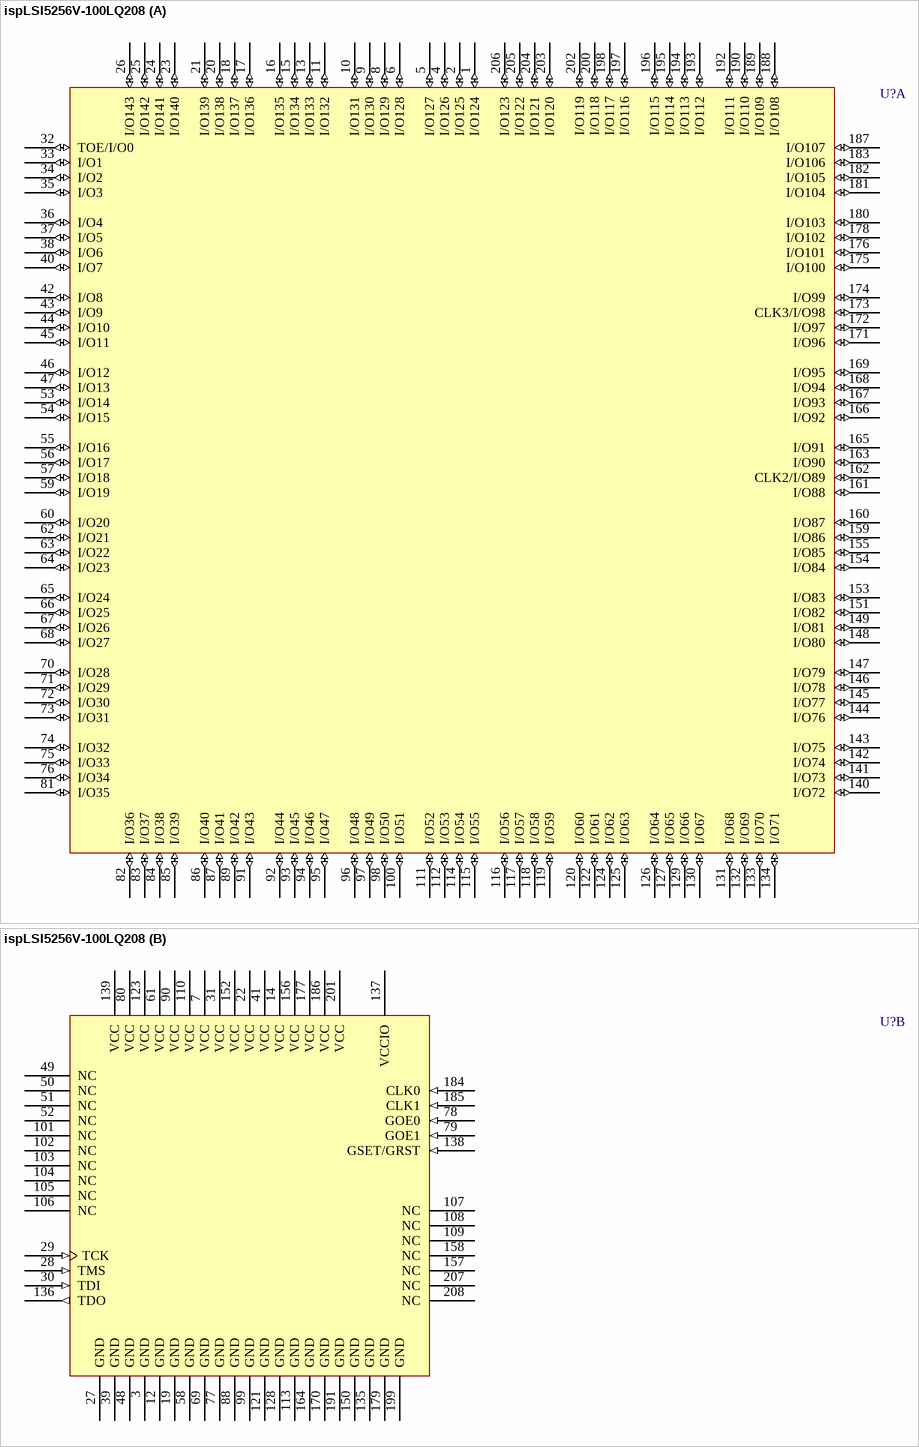
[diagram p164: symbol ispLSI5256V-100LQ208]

## ispLSI5256V-100LQ208
designator U?
In-System Programmable 3.3V SuperWIDE High-Density PLD; Note: I/O89 is multiplexed with CLK2; I/O98 is multiplexed with CLK3; I/O0 is multiplexed with TOE.
footprint PQFP208_N (Shrink QFP, 208-Leads, Body 28x28mm, Pitch 0.5mm, IPC Medium Density)
footprint PQFP208_L (Shrink QFP, 208-Leads, Body 28x28mm, Pitch 0.5mm, IPC High Density)
footprint PQFP208_M (Shrink QFP, 208-Leads, Body 28x28mm, Pitch 0.5mm, IPC Low Density)
3D model 5256V-PQFP208 (208-Pin Plastic Quad Flat Pack (PQFP208))
part A pins: 1 I/O124 (io), 2 I/O125 (io), 4 I/O126 (io), 5 I/O127 (io), 6 I/O128 (io), 8 I/O129 (io), 9 I/O130 (io), 10 I/O131 (io), 11 I/O132 (io), 13 I/O133 (io), 15 I/O134 (io), 16 I/O135 (io), 17 I/O136 (io), 18 I/O137 (io), 20 I/O138 (io), 21 I/O139 (io), 23 I/O140 (io), 24 I/O141 (io), 25 I/O142 (io), 26 I/O143 (io), 32 TOE/I/O0 (io), 33 I/O1 (io), 34 I/O2 (io), 35 I/O3 (io), 36 I/O4 (io), 37 I/O5 (io), 38 I/O6 (io), 40 I/O7 (io), 42 I/O8 (io), 43 I/O9 (io), 44 I/O10 (io), 45 I/O11 (io), 46 I/O12 (io), 47 I/O13 (io), 53 I/O14 (io), 54 I/O15 (io), 55 I/O16 (io), 56 I/O17 (io), 57 I/O18 (io), 59 I/O19 (io), 60 I/O20 (io), 62 I/O21 (io), 63 I/O22 (io), 64 I/O23 (io), 65 I/O24 (io), 66 I/O25 (io), 67 I/O26 (io), 68 I/O27 (io), 70 I/O28 (io), 71 I/O29 (io), 72 I/O30 (io), 73 I/O31 (io), 74 I/O32 (io), 75 I/O33 (io), 76 I/O34 (io), 81 I/O35 (io), 82 I/O36 (io), 83 I/O37 (io), 84 I/O38 (io), 85 I/O39 (io), 86 I/O40 (io), 87 I/O41 (io), 89 I/O42 (io), 91 I/O43 (io), 92 I/O44 (io), 93 I/O45 (io), 94 I/O46 (io), 95 I/O47 (io), 96 I/O48 (io), 97 I/O49 (io), 98 I/O50 (io), 100 I/O51 (io), 111 I/O52 (io), 112 I/O53 (io), 114 I/O54 (io), 115 I/O55 (io), 116 I/O56 (io), 117 I/O57 (io), 118 I/O58 (io), 119 I/O59 (io), 120 I/O60 (io), 122 I/O61 (io), 124 I/O62 (io), 125 I/O63 (io), 126 I/O64 (io), 127 I/O65 (io), 129 I/O66 (io), 130 I/O67 (io), 131 I/O68 (io), 132 I/O69 (io), 133 I/O70 (io), 134 I/O71 (io), 140 I/O72 (io), 141 I/O73 (io), 142 I/O74 (io), 143 I/O75 (io), 144 I/O76 (io), 145 I/O77 (io), 146 I/O78 (io), 147 I/O79 (io), 148 I/O80 (io), 149 I/O81 (io), 151 I/O82 (io), 153 I/O83 (io), 154 I/O84 (io), 155 I/O85 (io), 159 I/O86 (io), 160 I/O87 (io), 161 I/O88 (io), 162 CLK2/I/O89 (io), 163 I/O90 (io), 165 I/O91 (io), 166 I/O92 (io), 167 I/O93 (io), 168 I/O94 (io), 169 I/O95 (io), 171 I/O96 (io), 172 I/O97 (io), 173 CLK3/I/O98 (io), 174 I/O99 (io), 175 I/O100 (io), 176 I/O101 (io), 178 I/O102 (io), 180 I/O103 (io), 181 I/O104 (io), 182 I/O105 (io), 183 I/O106 (io), 187 I/O107 (io), 188 I/O108 (io), 189 I/O109 (io), 190 I/O110 (io), 192 I/O111 (io), 193 I/O112 (io), 194 I/O113 (io), 195 I/O114 (io), 196 I/O115 (io), 197 I/O116 (io), 198 I/O117 (io), 200 I/O118 (io), 202 I/O119 (io), 203 I/O120 (io), 204 I/O121 (io), 205 I/O122 (io), 206 I/O123 (io)
part B pins: 3 GND (power), 7 VCC (power), 12 GND (power), 14 VCC (power), 19 GND (power), 22 VCC (power), 27 GND (power), 28 TMS (in), 29 TCK (in), 30 TDI (in), 31 VCC (power), 39 GND (power), 41 VCC (power), 48 GND (power), 49 NC, 50 NC, 51 NC, 52 NC, 58 GND (power), 61 VCC (power), 69 GND (power), 77 GND (power), 78 GOE0 (in), 79 GOE1 (in), 80 VCC (power), 88 GND (power), 90 VCC (power), 99 GND (power), 101 NC, 102 NC, 103 NC, 104 NC, 105 NC, 106 NC, 107 NC, 108 NC, 109 NC, 110 VCC (power), 113 GND (power), 121 GND (power), 123 VCC (power), 128 GND (power), 135 GND (power), 136 TDO (out), 137 VCCIO (power), 138 GSET/GRST (in), 139 VCC (power), 150 GND (power), 152 VCC (power), 156 VCC (power), 157 NC, 158 NC, 164 GND (power), 170 GND (power), 177 VCC (power), 179 GND (power), 184 CLK0 (in), 185 CLK1 (in), 186 VCC (power), 191 GND (power), 199 GND (power), 201 VCC (power), 207 NC, 208 NC

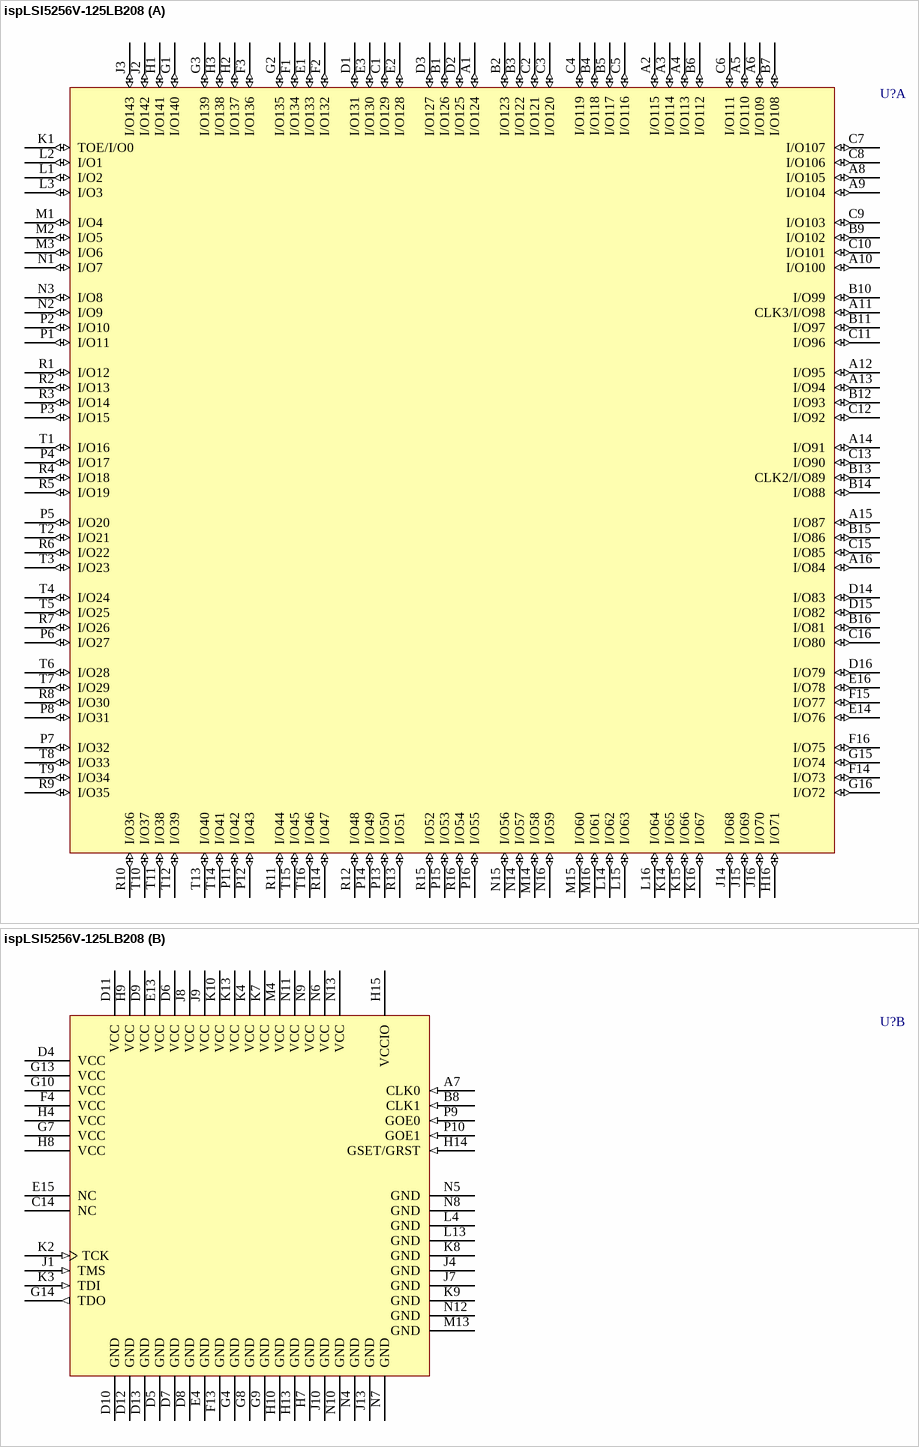
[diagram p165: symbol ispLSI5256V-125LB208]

## ispLSI5256V-125LB208
designator U?
In-System Programmable 3.3V SuperWIDE High-Density PLD; Note: I/O89 is multiplexed with CLK2; I/O98 is multiplexed with CLK3; I/O0 is multiplexed with TOE.
footprint fpBGA208 (BGA, 208-Leads, Body 17x17mm, Pitch 1mm)
3D model 5256V-fpBGA208 (208-Ball Fine Pitch Ball Grid Array (fpBGA208))
part A pins: A1 I/O124 (io), A2 I/O115 (io), A3 I/O114 (io), A4 I/O113 (io), A5 I/O110 (io), A6 I/O109 (io), A8 I/O105 (io), A9 I/O104 (io), A10 I/O100 (io), A11 CLK3/I/O98 (io), A12 I/O95 (io), A13 I/O94 (io), A14 I/O91 (io), A15 I/O87 (io), A16 I/O84 (io), B1 I/O126 (io), B2 I/O123 (io), B3 I/O122 (io), B4 I/O118 (io), B5 I/O117 (io), B6 I/O112 (io), B7 I/O108 (io), B9 I/O102 (io), B10 I/O99 (io), B11 I/O97 (io), B12 I/O93 (io), B13 CLK2/I/O89 (io), B14 I/O88 (io), B15 I/O86 (io), B16 I/O81 (io), C1 I/O129 (io), C2 I/O121 (io), C3 I/O120 (io), C4 I/O119 (io), C5 I/O116 (io), C6 I/O111 (io), C7 I/O107 (io), C8 I/O106 (io), C9 I/O103 (io), C10 I/O101 (io), C11 I/O96 (io), C12 I/O92 (io), C13 I/O90 (io), C15 I/O85 (io), C16 I/O80 (io), D1 I/O131 (io), D2 I/O125 (io), D3 I/O127 (io), D14 I/O83 (io), D15 I/O82 (io), D16 I/O79 (io), E1 I/O133 (io), E2 I/O128 (io), E3 I/O130 (io), E14 I/O76 (io), E16 I/O78 (io), F1 I/O134 (io), F2 I/O132 (io), F3 I/O136 (io), F14 I/O73 (io), F15 I/O77 (io), F16 I/O75 (io), G1 I/O140 (io), G2 I/O135 (io), G3 I/O139 (io), G15 I/O74 (io), G16 I/O72 (io), H1 I/O141 (io), H2 I/O137 (io), H3 I/O138 (io), H16 I/O71 (io), J2 I/O142 (io), J3 I/O143 (io), J14 I/O68 (io), J15 I/O69 (io), J16 I/O70 (io), K1 TOE/I/O0 (io), K14 I/O65 (io), K15 I/O66 (io), K16 I/O67 (io), L1 I/O2 (io), L2 I/O1 (io), L3 I/O3 (io), L14 I/O62 (io), L15 I/O63 (io), L16 I/O64 (io), M1 I/O4 (io), M2 I/O5 (io), M3 I/O6 (io), M14 I/O58 (io), M15 I/O60 (io), M16 I/O61 (io), N1 I/O7 (io), N2 I/O9 (io), N3 I/O8 (io), N14 I/O57 (io), N15 I/O56 (io), N16 I/O59 (io), P1 I/O11 (io), P2 I/O10 (io), P3 I/O15 (io), P4 I/O17 (io), P5 I/O20 (io), P6 I/O27 (io), P7 I/O32 (io), P8 I/O31 (io), P11 I/O42 (io), P12 I/O43 (io), P13 I/O50 (io), P14 I/O49 (io), P15 I/O53 (io), P16 I/O55 (io), R1 I/O12 (io), R2 I/O13 (io), R3 I/O14 (io), R4 I/O18 (io), R5 I/O19 (io), R6 I/O22 (io), R7 I/O26 (io), R8 I/O30 (io), R9 I/O35 (io), R10 I/O36 (io), R11 I/O44 (io), R12 I/O48 (io), R13 I/O51 (io), R14 I/O47 (io), R15 I/O52 (io), R16 I/O54 (io), T1 I/O16 (io), T2 I/O21 (io), T3 I/O23 (io), T4 I/O24 (io), T5 I/O25 (io), T6 I/O28 (io), T7 I/O29 (io), T8 I/O33 (io), T9 I/O34 (io), T10 I/O37 (io), T11 I/O38 (io), T12 I/O39 (io), T13 I/O40 (io), T14 I/O41 (io), T15 I/O45 (io), T16 I/O46 (io)
part B pins: A7 CLK0 (in), B8 CLK1 (in), C14 NC, D4 VCC (power), D5 GND (power), D6 VCC (power), D7 GND (power), D8 GND (power), D9 VCC (power), D10 GND (power), D11 VCC (power), D12 GND (power), D13 GND (power), E4 GND (power), E13 VCC (power), E15 NC, F4 VCC (power), F13 GND (power), G4 GND (power), G7 VCC (power), G8 GND (power), G9 GND (power), G10 VCC (power), G13 VCC (power), G14 TDO (out), H4 VCC (power), H7 GND (power), H8 VCC (power), H9 VCC (power), H10 GND (power), H13 GND (power), H14 GSET/GRST (in), H15 VCCIO (power), J1 TMS (in), J4 GND (power), J7 GND (power), J8 VCC (power), J9 VCC (power), J10 GND (power), J13 GND (power), K2 TCK (in), K3 TDI (in), K4 VCC (power), K7 VCC (power), K8 GND (power), K9 GND (power), K10 VCC (power), K13 VCC (power), L4 GND (power), L13 GND (power), M4 VCC (power), M13 GND (power), N4 GND (power), N5 GND (power), N6 VCC (power), N7 GND (power), N8 GND (power), N9 VCC (power), N10 GND (power), N11 VCC (power), N12 GND (power), N13 VCC (power), P9 GOE0 (in), P10 GOE1 (in)

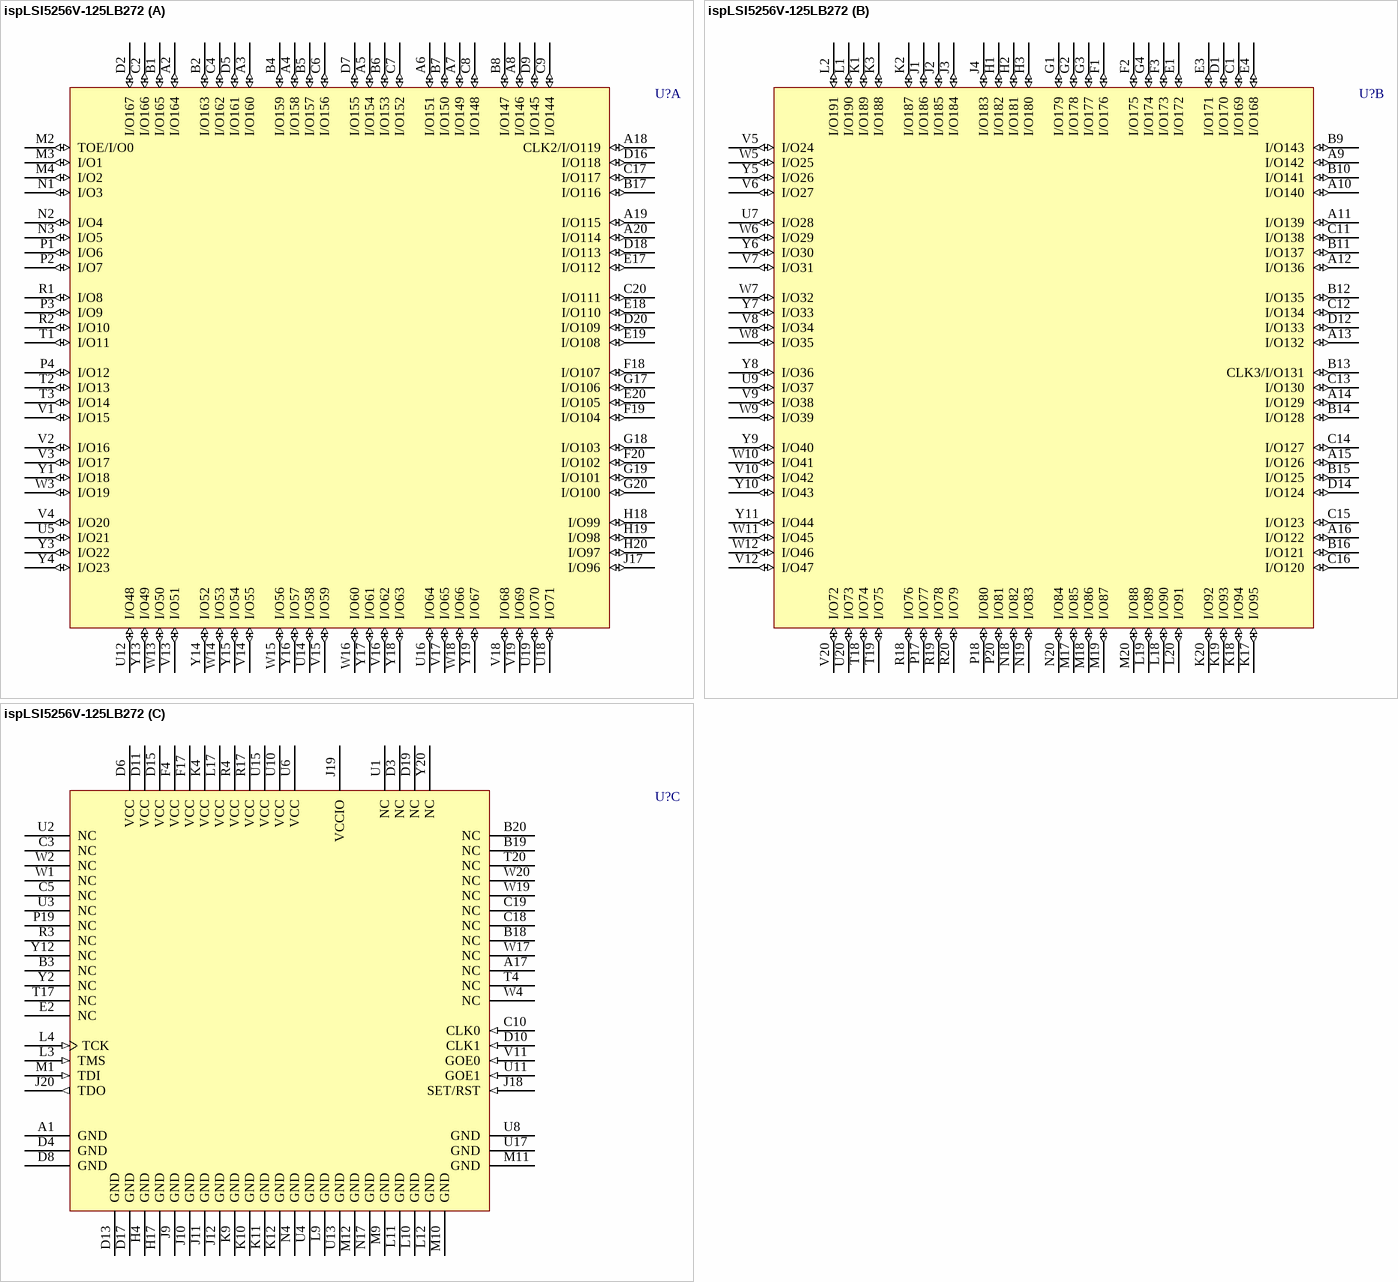
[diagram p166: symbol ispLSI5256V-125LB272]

## ispLSI5256V-125LB272
designator U?
In-System Programmable 3.3V SuperWIDE High-Density PLD; Note: I/O119 is multiplexed with CLK2; I/O131 is multiplexed with CLK3; I/O0 is multiplexed with TOE.
footprint BGA272 (BGA, 272-Leads, Body 27x27mm, Pitch 1.27mm)
3D model 5256V-BGA272 (272-Ball Ball Grid Array (BGA272))
part A pins: A2 I/O164 (io), A3 I/O160 (io), A4 I/O158 (io), A5 I/O154 (io), A6 I/O151 (io), A7 I/O149 (io), A8 I/O146 (io), A18 CLK2/I/O119 (io), A19 I/O115 (io), A20 I/O114 (io), B1 I/O165 (io), B2 I/O163 (io), B4 I/O159 (io), B5 I/O157 (io), B6 I/O153 (io), B7 I/O150 (io), B8 I/O147 (io), B17 I/O116 (io), C2 I/O166 (io), C4 I/O162 (io), C6 I/O156 (io), C7 I/O152 (io), C8 I/O148 (io), C9 I/O144 (io), C17 I/O117 (io), C20 I/O111 (io), D2 I/O167 (io), D5 I/O161 (io), D7 I/O155 (io), D9 I/O145 (io), D16 I/O118 (io), D18 I/O113 (io), D20 I/O109 (io), E17 I/O112 (io), E18 I/O110 (io), E19 I/O108 (io), E20 I/O105 (io), F18 I/O107 (io), F19 I/O104 (io), F20 I/O102 (io), G17 I/O106 (io), G18 I/O103 (io), G19 I/O101 (io), G20 I/O100 (io), H18 I/O99 (io), H19 I/O98 (io), H20 I/O97 (io), J17 I/O96 (io), M2 TOE/I/O0 (io), M3 I/O1 (io), M4 I/O2 (io), N1 I/O3 (io), N2 I/O4 (io), N3 I/O5 (io), P1 I/O6 (io), P2 I/O7 (io), P3 I/O9 (io), P4 I/O12 (io), R1 I/O8 (io), R2 I/O10 (io), T1 I/O11 (io), T2 I/O13 (io), T3 I/O14 (io), U5 I/O21 (io), U12 I/O48 (io), U14 I/O58 (io), U16 I/O64 (io), U18 I/O71 (io), U19 I/O70 (io), V1 I/O15 (io), V2 I/O16 (io), V3 I/O17 (io), V4 I/O20 (io), V13 I/O51 (io), V14 I/O55 (io), V15 I/O59 (io), V16 I/O62 (io), V17 I/O65 (io), V18 I/O68 (io), V19 I/O69 (io), W3 I/O19 (io), W13 I/O50 (io), W14 I/O53 (io), W15 I/O56 (io), W16 I/O60 (io), W18 I/O66 (io), Y1 I/O18 (io), Y3 I/O22 (io), Y4 I/O23 (io), Y13 I/O49 (io), Y14 I/O52 (io), Y15 I/O54 (io), Y16 I/O57 (io), Y17 I/O61 (io), Y18 I/O63 (io), Y19 I/O67 (io)
part B pins: A9 I/O142 (io), A10 I/O140 (io), A11 I/O139 (io), A12 I/O136 (io), A13 I/O132 (io), A14 I/O129 (io), A15 I/O126 (io), A16 I/O122 (io), B9 I/O143 (io), B10 I/O141 (io), B11 I/O137 (io), B12 I/O135 (io), B13 CLK3/I/O131 (io), B14 I/O128 (io), B15 I/O125 (io), B16 I/O121 (io), C1 I/O169 (io), C11 I/O138 (io), C12 I/O134 (io), C13 I/O130 (io), C14 I/O127 (io), C15 I/O123 (io), C16 I/O120 (io), D1 I/O170 (io), D12 I/O133 (io), D14 I/O124 (io), E1 I/O172 (io), E3 I/O171 (io), E4 I/O168 (io), F1 I/O176 (io), F2 I/O175 (io), F3 I/O173 (io), G1 I/O179 (io), G2 I/O178 (io), G3 I/O177 (io), G4 I/O174 (io), H1 I/O182 (io), H2 I/O181 (io), H3 I/O180 (io), J1 I/O186 (io), J2 I/O185 (io), J3 I/O184 (io), J4 I/O183 (io), K1 I/O189 (io), K2 I/O187 (io), K3 I/O188 (io), K17 I/O95 (io), K18 I/O94 (io), K19 I/O93 (io), K20 I/O92 (io), L1 I/O190 (io), L2 I/O191 (io), L18 I/O90 (io), L19 I/O89 (io), L20 I/O91 (io), M17 I/O85 (io), M18 I/O86 (io), M19 I/O87 (io), M20 I/O88 (io), N18 I/O82 (io), N19 I/O83 (io), N20 I/O84 (io), P17 I/O77 (io), P18 I/O80 (io), P20 I/O81 (io), R18 I/O76 (io), R19 I/O78 (io), R20 I/O79 (io), T18 I/O74 (io), T19 I/O75 (io), U7 I/O28 (io), U9 I/O37 (io), U20 I/O73 (io), V5 I/O24 (io), V6 I/O27 (io), V7 I/O31 (io), V8 I/O34 (io), V9 I/O38 (io), V10 I/O42 (io), V12 I/O47 (io), V20 I/O72 (io), W5 I/O25 (io), W6 I/O29 (io), W7 I/O32 (io), W8 I/O35 (io), W9 I/O39 (io), W10 I/O41 (io), W11 I/O45 (io), W12 I/O46 (io), Y5 I/O26 (io), Y6 I/O30 (io), Y7 I/O33 (io), Y8 I/O36 (io), Y9 I/O40 (io), Y10 I/O43 (io), Y11 I/O44 (io)
part C pins: A1 GND (power), A17 NC, B3 NC, B18 NC, B19 NC, B20 NC, C3 NC, C5 NC, C10 CLK0 (in), C18 NC, C19 NC, D3 NC, D4 GND (power), D6 VCC (power), D8 GND (power), D10 CLK1 (in), D11 VCC (power), D13 GND (power), D15 VCC (power), D17 GND (power), D19 NC, E2 NC, F4 VCC (power), F17 VCC (power), H4 GND (power), H17 GND (power), J9 GND (power), J10 GND (power), J11 GND (power), J12 GND (power), J18 SET/RST (in), J19 VCCIO (power), J20 TDO (out), K4 VCC (power), K9 GND (power), K10 GND (power), K11 GND (power), K12 GND (power), L3 TMS (in), L4 TCK (in), L9 GND (power), L10 GND (power), L11 GND (power), L12 GND (power), L17 VCC (power), M1 TDI (in), M9 GND (power), M10 GND (power), M11 GND (power), M12 GND (power), N4 GND (power), N17 GND (power), P19 NC, R3 NC, R4 VCC (power), R17 VCC (power), T4 NC, T17 NC, T20 NC, U1 NC, U2 NC, U3 NC, U4 GND (power), U6 VCC (power), U8 GND (power), U10 VCC (power), U11 GOE1 (in), U13 GND (power), U15 VCC (power), U17 GND (power), V11 GOE0 (in), W1 NC, W2 NC, W4 NC, W17 NC, W19 NC, W20 NC, Y2 NC, Y12 NC, Y20 NC

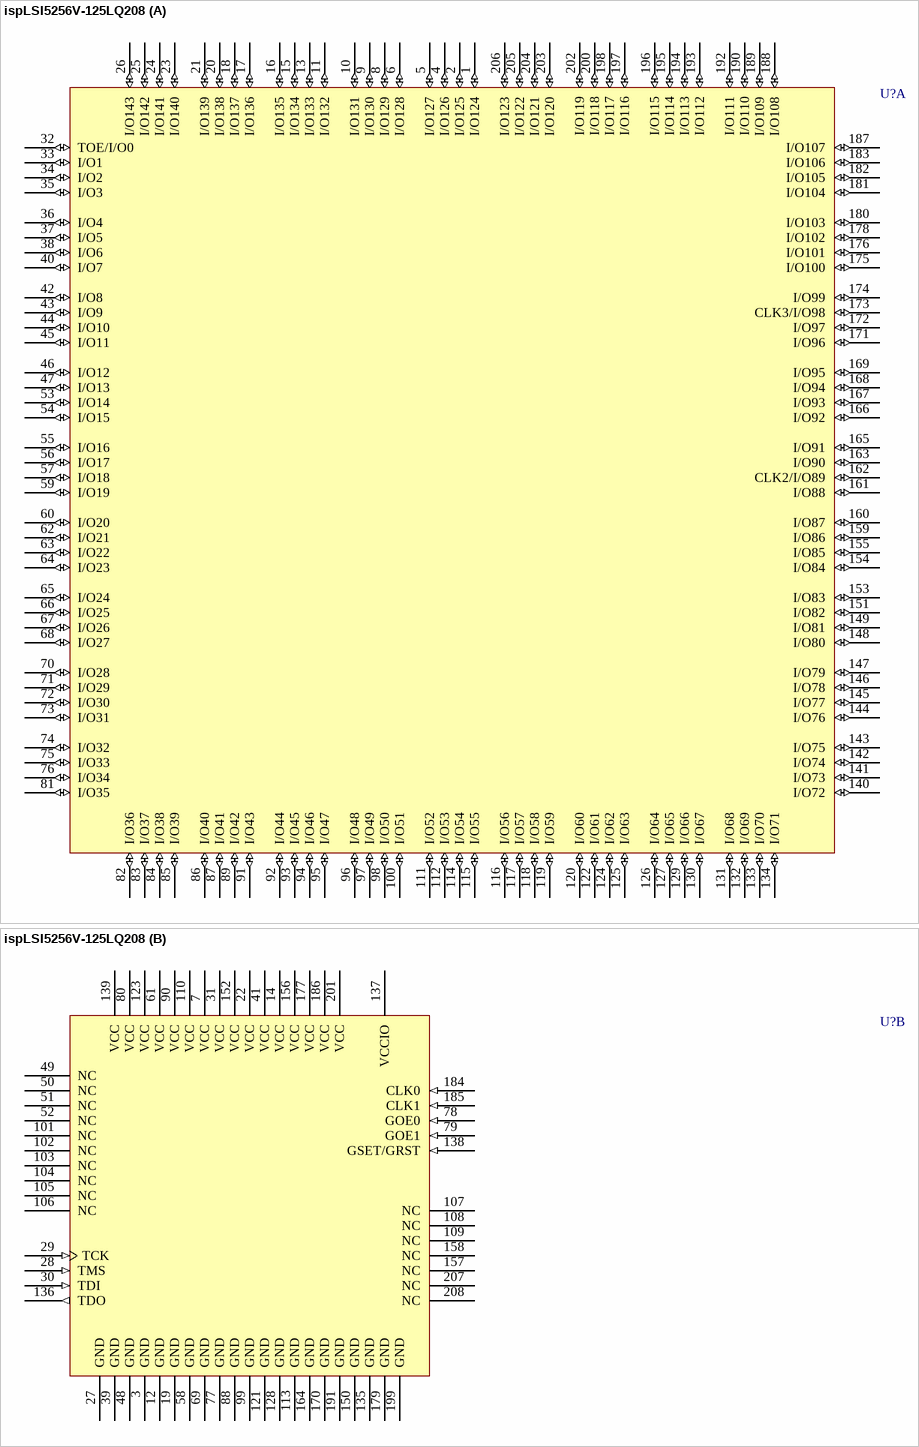
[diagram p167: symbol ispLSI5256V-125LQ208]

## ispLSI5256V-125LQ208
designator U?
In-System Programmable 3.3V SuperWIDE High-Density PLD; Note: I/O89 is multiplexed with CLK2; I/O98 is multiplexed with CLK3; I/O0 is multiplexed with TOE.
footprint PQFP208_N (Shrink QFP, 208-Leads, Body 28x28mm, Pitch 0.5mm, IPC Medium Density)
footprint PQFP208_L (Shrink QFP, 208-Leads, Body 28x28mm, Pitch 0.5mm, IPC High Density)
footprint PQFP208_M (Shrink QFP, 208-Leads, Body 28x28mm, Pitch 0.5mm, IPC Low Density)
3D model 5256V-PQFP208 (208-Pin Plastic Quad Flat Pack (PQFP208))
part A pins: 1 I/O124 (io), 2 I/O125 (io), 4 I/O126 (io), 5 I/O127 (io), 6 I/O128 (io), 8 I/O129 (io), 9 I/O130 (io), 10 I/O131 (io), 11 I/O132 (io), 13 I/O133 (io), 15 I/O134 (io), 16 I/O135 (io), 17 I/O136 (io), 18 I/O137 (io), 20 I/O138 (io), 21 I/O139 (io), 23 I/O140 (io), 24 I/O141 (io), 25 I/O142 (io), 26 I/O143 (io), 32 TOE/I/O0 (io), 33 I/O1 (io), 34 I/O2 (io), 35 I/O3 (io), 36 I/O4 (io), 37 I/O5 (io), 38 I/O6 (io), 40 I/O7 (io), 42 I/O8 (io), 43 I/O9 (io), 44 I/O10 (io), 45 I/O11 (io), 46 I/O12 (io), 47 I/O13 (io), 53 I/O14 (io), 54 I/O15 (io), 55 I/O16 (io), 56 I/O17 (io), 57 I/O18 (io), 59 I/O19 (io), 60 I/O20 (io), 62 I/O21 (io), 63 I/O22 (io), 64 I/O23 (io), 65 I/O24 (io), 66 I/O25 (io), 67 I/O26 (io), 68 I/O27 (io), 70 I/O28 (io), 71 I/O29 (io), 72 I/O30 (io), 73 I/O31 (io), 74 I/O32 (io), 75 I/O33 (io), 76 I/O34 (io), 81 I/O35 (io), 82 I/O36 (io), 83 I/O37 (io), 84 I/O38 (io), 85 I/O39 (io), 86 I/O40 (io), 87 I/O41 (io), 89 I/O42 (io), 91 I/O43 (io), 92 I/O44 (io), 93 I/O45 (io), 94 I/O46 (io), 95 I/O47 (io), 96 I/O48 (io), 97 I/O49 (io), 98 I/O50 (io), 100 I/O51 (io), 111 I/O52 (io), 112 I/O53 (io), 114 I/O54 (io), 115 I/O55 (io), 116 I/O56 (io), 117 I/O57 (io), 118 I/O58 (io), 119 I/O59 (io), 120 I/O60 (io), 122 I/O61 (io), 124 I/O62 (io), 125 I/O63 (io), 126 I/O64 (io), 127 I/O65 (io), 129 I/O66 (io), 130 I/O67 (io), 131 I/O68 (io), 132 I/O69 (io), 133 I/O70 (io), 134 I/O71 (io), 140 I/O72 (io), 141 I/O73 (io), 142 I/O74 (io), 143 I/O75 (io), 144 I/O76 (io), 145 I/O77 (io), 146 I/O78 (io), 147 I/O79 (io), 148 I/O80 (io), 149 I/O81 (io), 151 I/O82 (io), 153 I/O83 (io), 154 I/O84 (io), 155 I/O85 (io), 159 I/O86 (io), 160 I/O87 (io), 161 I/O88 (io), 162 CLK2/I/O89 (io), 163 I/O90 (io), 165 I/O91 (io), 166 I/O92 (io), 167 I/O93 (io), 168 I/O94 (io), 169 I/O95 (io), 171 I/O96 (io), 172 I/O97 (io), 173 CLK3/I/O98 (io), 174 I/O99 (io), 175 I/O100 (io), 176 I/O101 (io), 178 I/O102 (io), 180 I/O103 (io), 181 I/O104 (io), 182 I/O105 (io), 183 I/O106 (io), 187 I/O107 (io), 188 I/O108 (io), 189 I/O109 (io), 190 I/O110 (io), 192 I/O111 (io), 193 I/O112 (io), 194 I/O113 (io), 195 I/O114 (io), 196 I/O115 (io), 197 I/O116 (io), 198 I/O117 (io), 200 I/O118 (io), 202 I/O119 (io), 203 I/O120 (io), 204 I/O121 (io), 205 I/O122 (io), 206 I/O123 (io)
part B pins: 3 GND (power), 7 VCC (power), 12 GND (power), 14 VCC (power), 19 GND (power), 22 VCC (power), 27 GND (power), 28 TMS (in), 29 TCK (in), 30 TDI (in), 31 VCC (power), 39 GND (power), 41 VCC (power), 48 GND (power), 49 NC, 50 NC, 51 NC, 52 NC, 58 GND (power), 61 VCC (power), 69 GND (power), 77 GND (power), 78 GOE0 (in), 79 GOE1 (in), 80 VCC (power), 88 GND (power), 90 VCC (power), 99 GND (power), 101 NC, 102 NC, 103 NC, 104 NC, 105 NC, 106 NC, 107 NC, 108 NC, 109 NC, 110 VCC (power), 113 GND (power), 121 GND (power), 123 VCC (power), 128 GND (power), 135 GND (power), 136 TDO (out), 137 VCCIO (power), 138 GSET/GRST (in), 139 VCC (power), 150 GND (power), 152 VCC (power), 156 VCC (power), 157 NC, 158 NC, 164 GND (power), 170 GND (power), 177 VCC (power), 179 GND (power), 184 CLK0 (in), 185 CLK1 (in), 186 VCC (power), 191 GND (power), 199 GND (power), 201 VCC (power), 207 NC, 208 NC

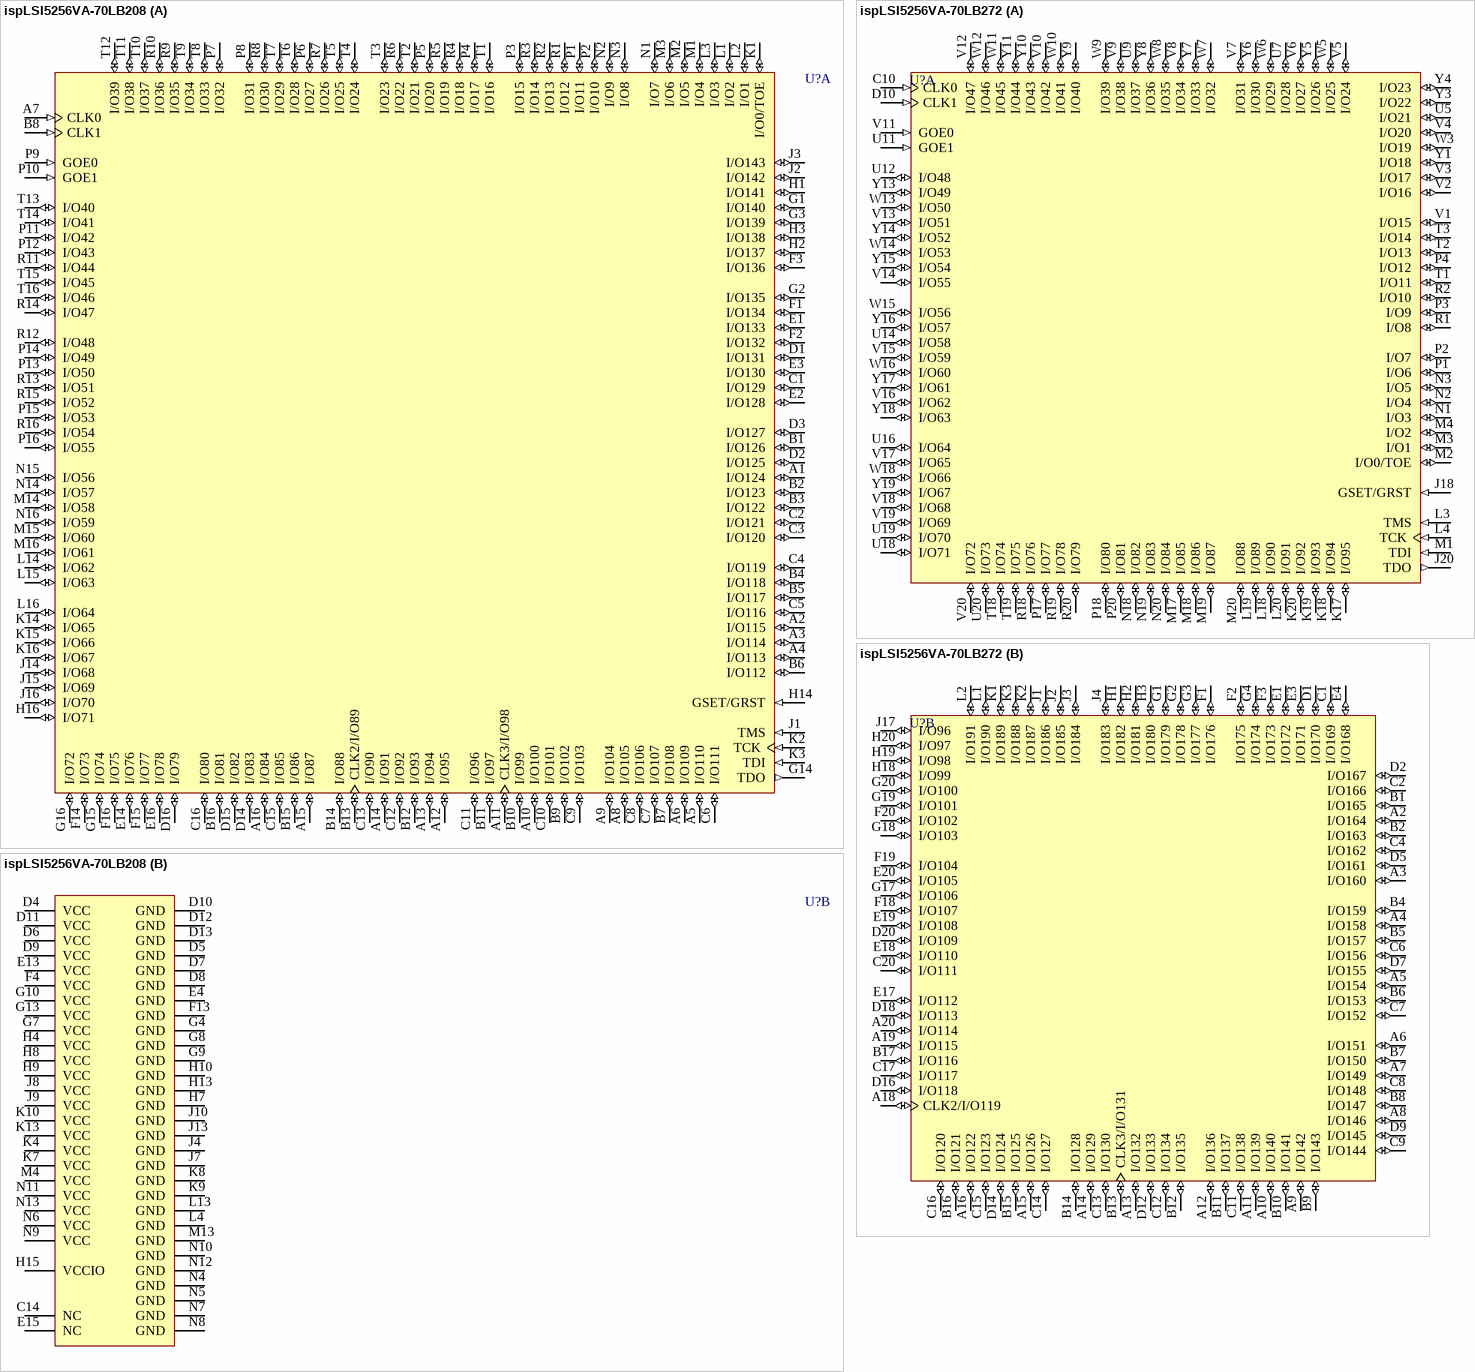
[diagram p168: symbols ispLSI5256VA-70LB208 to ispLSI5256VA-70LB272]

## ispLSI5256VA-70LB208
designator U?
In-System Programmable 3.3V SuperWIDE High Density PLD
footprint fpBGA208 (BGA, 208-Leads, Body 17x17mm, Pitch 1mm)
3D model 5384VA-fpBGA208 (208-Ball Fine Pitch Ball Grid Array (fpBGA208))
part A pins: A1 I/O124 (io), A2 I/O115 (io), A3 I/O114 (io), A4 I/O113 (io), A5 I/O110 (io), A6 I/O109 (io), A7 CLK0 (in), A8 I/O105 (io), A9 I/O104 (io), A10 I/O100 (io), A11 CLK3/I/O98 (io), A12 I/O95 (io), A13 I/O94 (io), A14 I/O91 (io), A15 I/O87 (io), A16 I/O84 (io), B1 I/O126 (io), B2 I/O123 (io), B3 I/O122 (io), B4 I/O118 (io), B5 I/O117 (io), B6 I/O112 (io), B7 I/O108 (io), B8 CLK1 (in), B9 I/O102 (io), B10 I/O99 (io), B11 I/O97 (io), B12 I/O93 (io), B13 CLK2/I/O89 (io), B14 I/O88 (io), B15 I/O86 (io), B16 I/O81 (io), C1 I/O129 (io), C2 I/O121 (io), C3 I/O120 (io), C4 I/O119 (io), C5 I/O116 (io), C6 I/O111 (io), C7 I/O107 (io), C8 I/O106 (io), C9 I/O103 (io), C10 I/O101 (io), C11 I/O96 (io), C12 I/O92 (io), C13 I/O90 (io), C15 I/O85 (io), C16 I/O80 (io), D1 I/O131 (io), D2 I/O125 (io), D3 I/O127 (io), D14 I/O83 (io), D15 I/O82 (io), D16 I/O79 (io), E1 I/O133 (io), E2 I/O128 (io), E3 I/O130 (io), E14 I/O76 (io), E16 I/O78 (io), F1 I/O134 (io), F2 I/O132 (io), F3 I/O136 (io), F14 I/O73 (io), F15 I/O77 (io), F16 I/O75 (io), G1 I/O140 (io), G2 I/O135 (io), G3 I/O139 (io), G14 TDO (out), G15 I/O74 (io), G16 I/O72 (io), H1 I/O141 (io), H2 I/O137 (io), H3 I/O138 (io), H14 GSET/GRST (in), H16 I/O71 (io), J1 TMS (in), J2 I/O142 (io), J3 I/O143 (io), J14 I/O68 (io), J15 I/O69 (io), J16 I/O70 (io), K1 I/O0/TOE (io), K2 TCK (in), K3 TDI (in), K14 I/O65 (io), K15 I/O66 (io), K16 I/O67 (io), L1 I/O2 (io), L2 I/O1 (io), L3 I/O3 (io), L14 I/O62 (io), L15 I/O63 (io), L16 I/O64 (io), M1 I/O4 (io), M2 I/O5 (io), M3 I/O6 (io), M14 I/O58 (io), M15 I/O60 (io), M16 I/O61 (io), N1 I/O7 (io), N2 I/O9 (io), N3 I/O8 (io), N14 I/O57 (io), N15 I/O56 (io), N16 I/O59 (io), P1 I/O11 (io), P2 I/O10 (io), P3 I/O15 (io), P4 I/O17 (io), P5 I/O20 (io), P6 I/O27 (io), P7 I/O32 (io), P8 I/O31 (io), P9 GOE0 (in), P10 GOE1 (in), P11 I/O42 (io), P12 I/O43 (io), P13 I/O50 (io), P14 I/O49 (io), P15 I/O53 (io), P16 I/O55 (io), R1 I/O12 (io), R2 I/O13 (io), R3 I/O14 (io), R4 I/O18 (io), R5 I/O19 (io), R6 I/O22 (io), R7 I/O26 (io), R8 I/O30 (io), R9 I/O35 (io), R10 I/O36 (io), R11 I/O44 (io), R12 I/O48 (io), R13 I/O51 (io), R14 I/O47 (io), R15 I/O52 (io), R16 I/O54 (io), T1 I/O16 (io), T2 I/O21 (io), T3 I/O23 (io), T4 I/O24 (io), T5 I/O25 (io), T6 I/O28 (io), T7 I/O29 (io), T8 I/O33 (io), T9 I/O34 (io), T10 I/O37 (io), T11 I/O38 (io), T12 I/O39 (io), T13 I/O40 (io), T14 I/O41 (io), T15 I/O45 (io), T16 I/O46 (io)
part B pins: C14 NC, D4 VCC (power), D5 GND (power), D6 VCC (power), D7 GND (power), D8 GND (power), D9 VCC (power), D10 GND (power), D11 VCC (power), D12 GND (power), D13 GND (power), E4 GND (power), E13 VCC (power), E15 NC, F4 VCC (power), F13 GND (power), G4 GND (power), G7 VCC (power), G8 GND (power), G9 GND (power), G10 VCC (power), G13 VCC (power), H4 VCC (power), H7 GND (power), H8 VCC (power), H9 VCC (power), H10 GND (power), H13 GND (power), H15 VCCIO (power), J4 GND (power), J7 GND (power), J8 VCC (power), J9 VCC (power), J10 GND (power), J13 GND (power), K4 VCC (power), K7 VCC (power), K8 GND (power), K9 GND (power), K10 VCC (power), K13 VCC (power), L4 GND (power), L13 GND (power), M4 VCC (power), M13 GND (power), N4 GND (power), N5 GND (power), N6 VCC (power), N7 GND (power), N8 GND (power), N9 VCC (power), N10 GND (power), N11 VCC (power), N12 GND (power), N13 VCC (power)

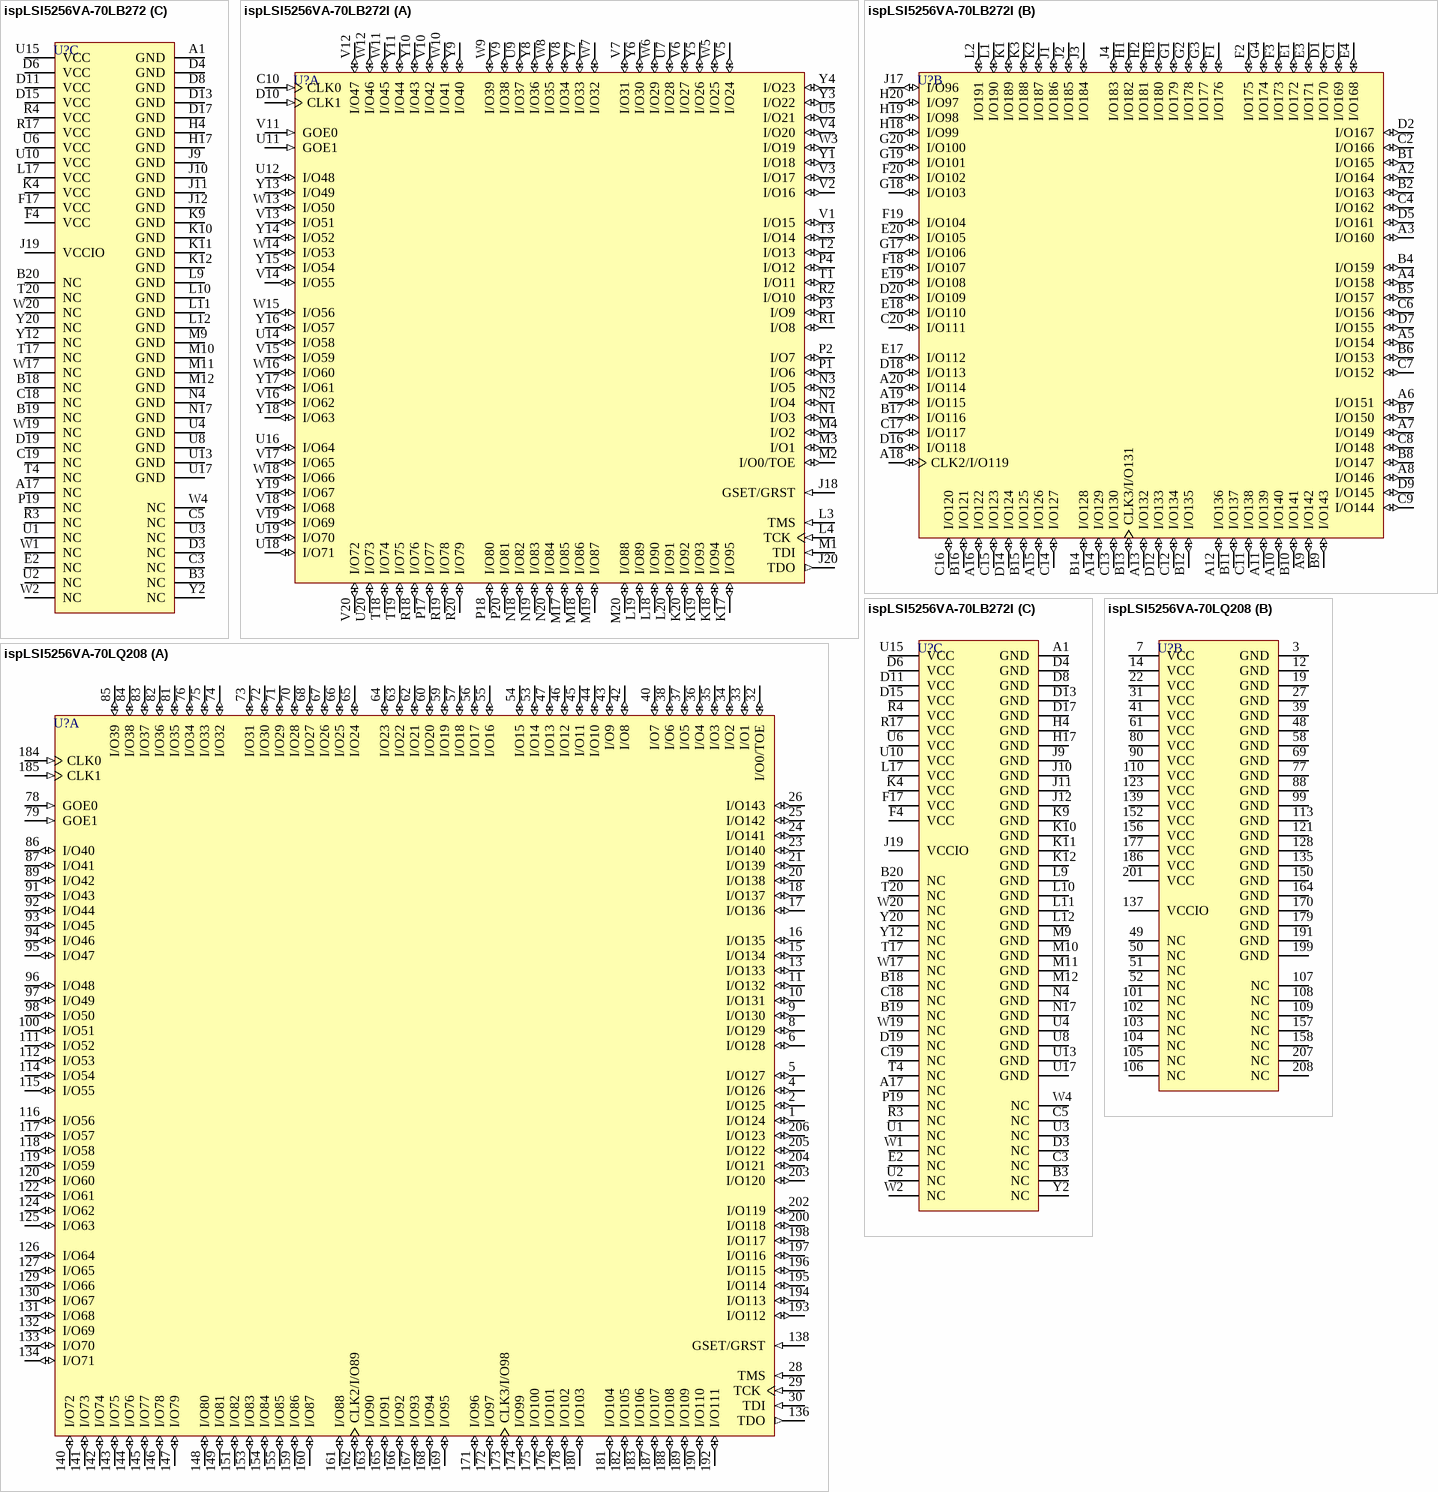
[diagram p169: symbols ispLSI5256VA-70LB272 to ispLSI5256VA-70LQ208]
